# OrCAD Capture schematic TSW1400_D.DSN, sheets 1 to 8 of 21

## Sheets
1 BUTTON, SWITCH, LEDS: size B; title: BUTTONS, SWITCHES, LEDS; rev: D; note: TSW1400
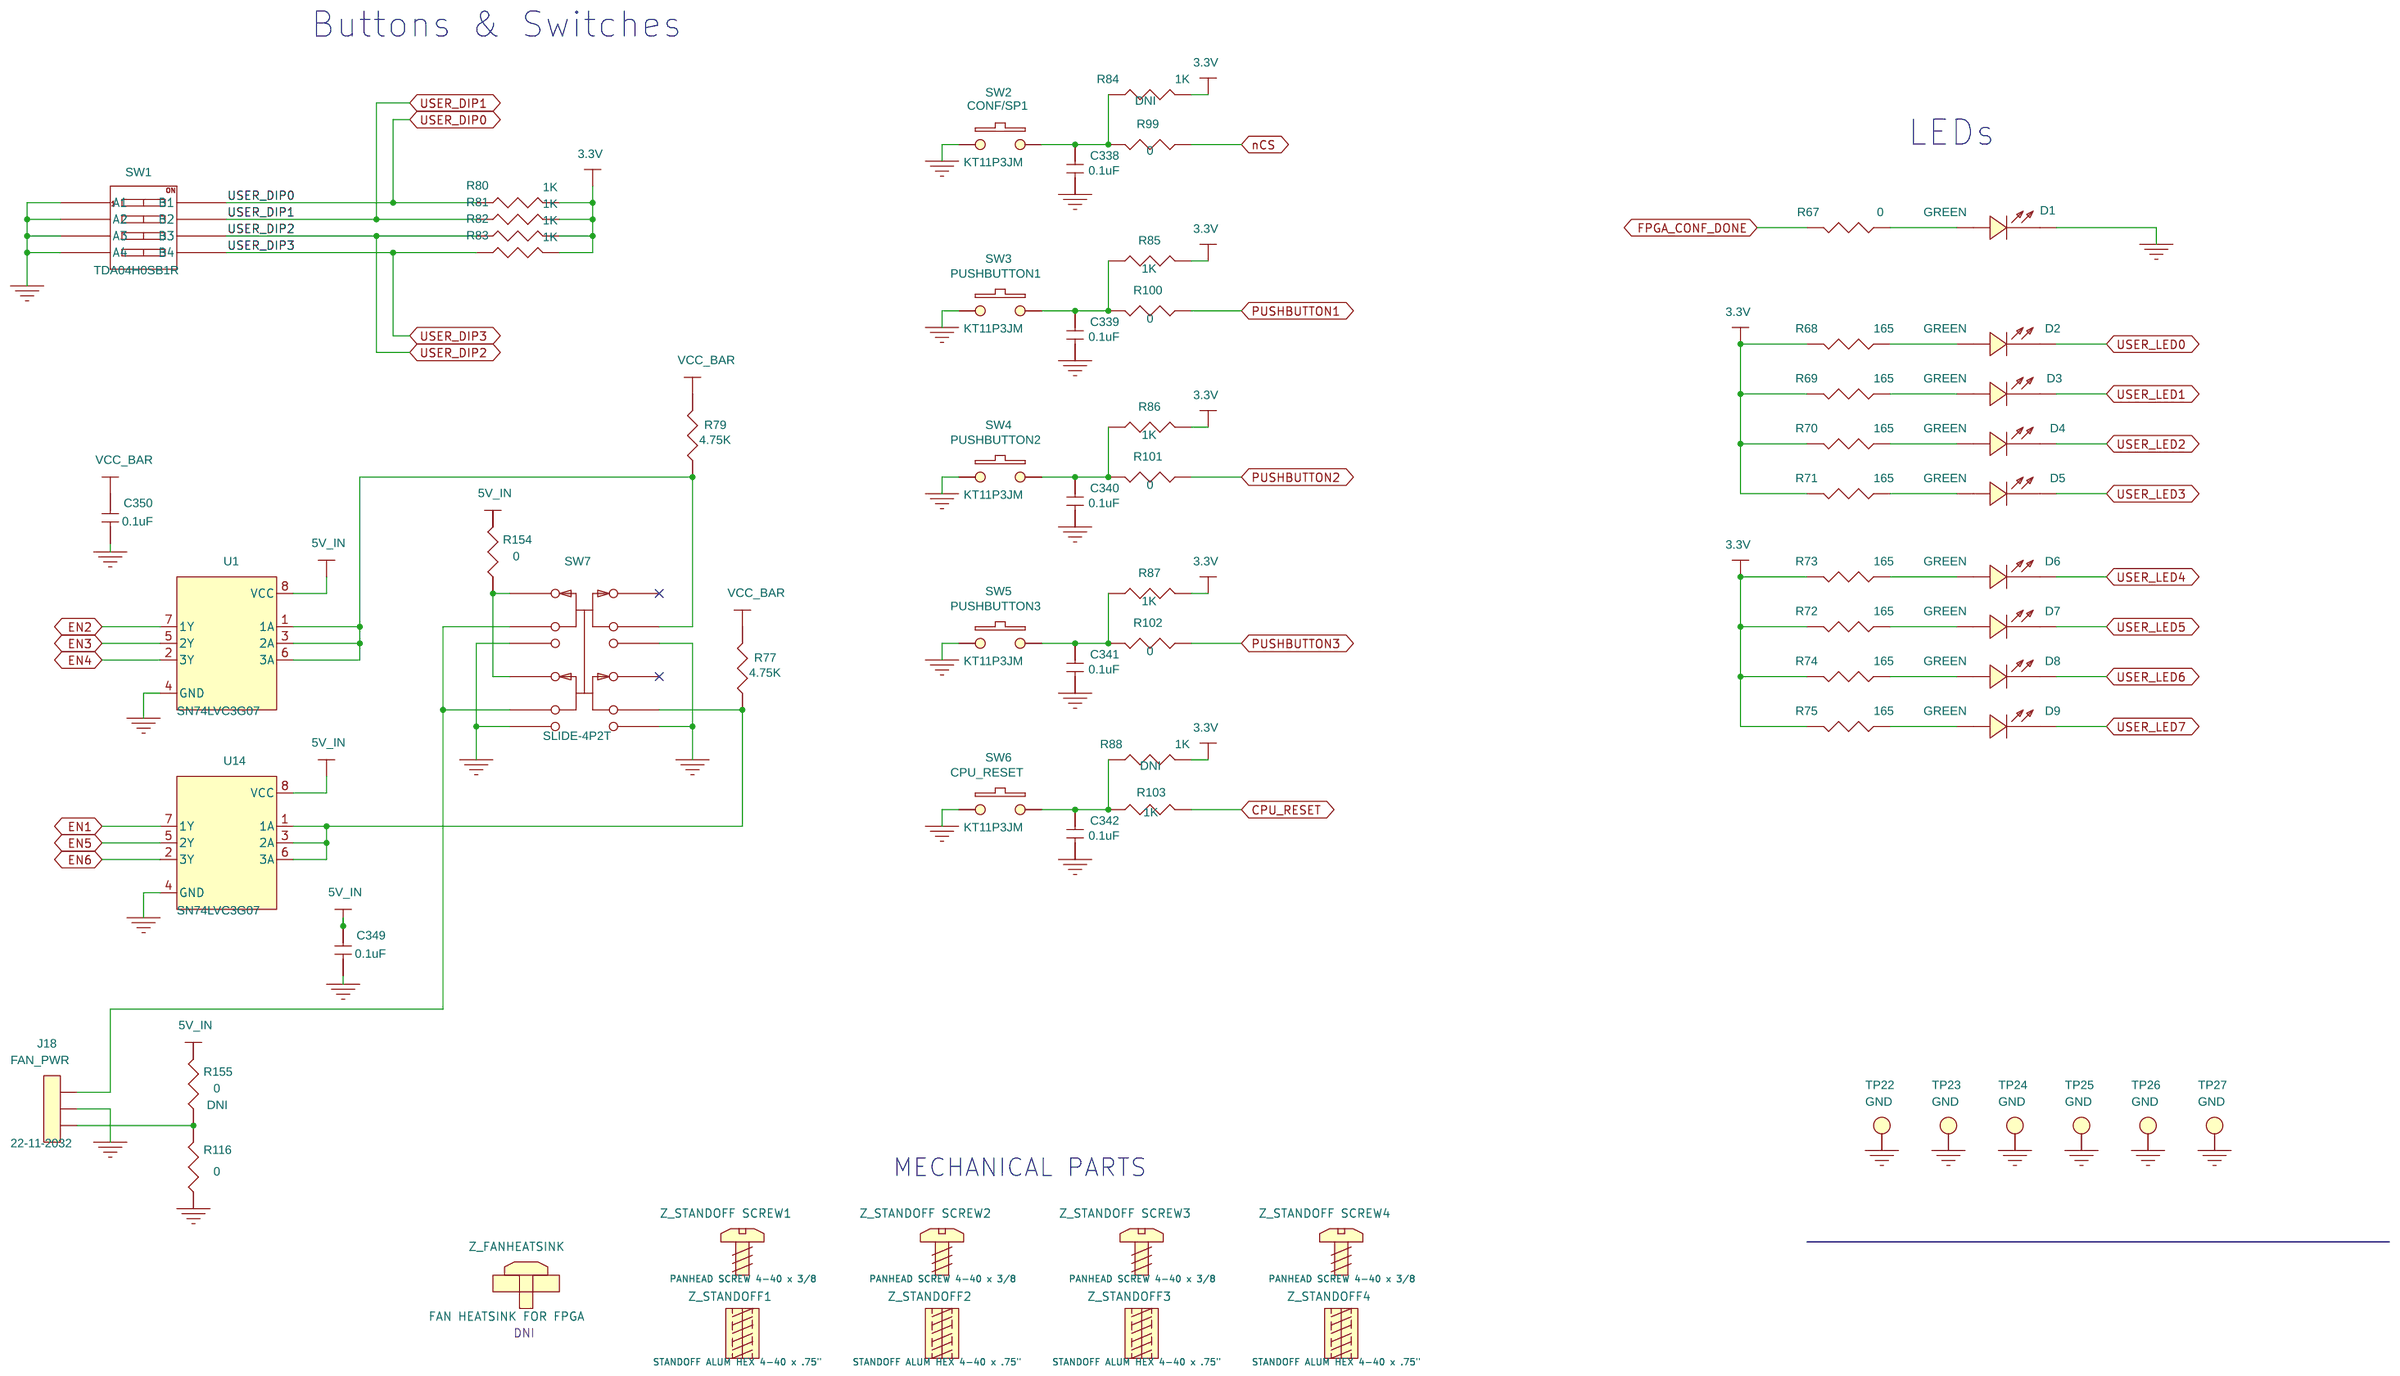
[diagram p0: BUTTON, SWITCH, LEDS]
2 CMOS Header: size B; title: CMOS Header
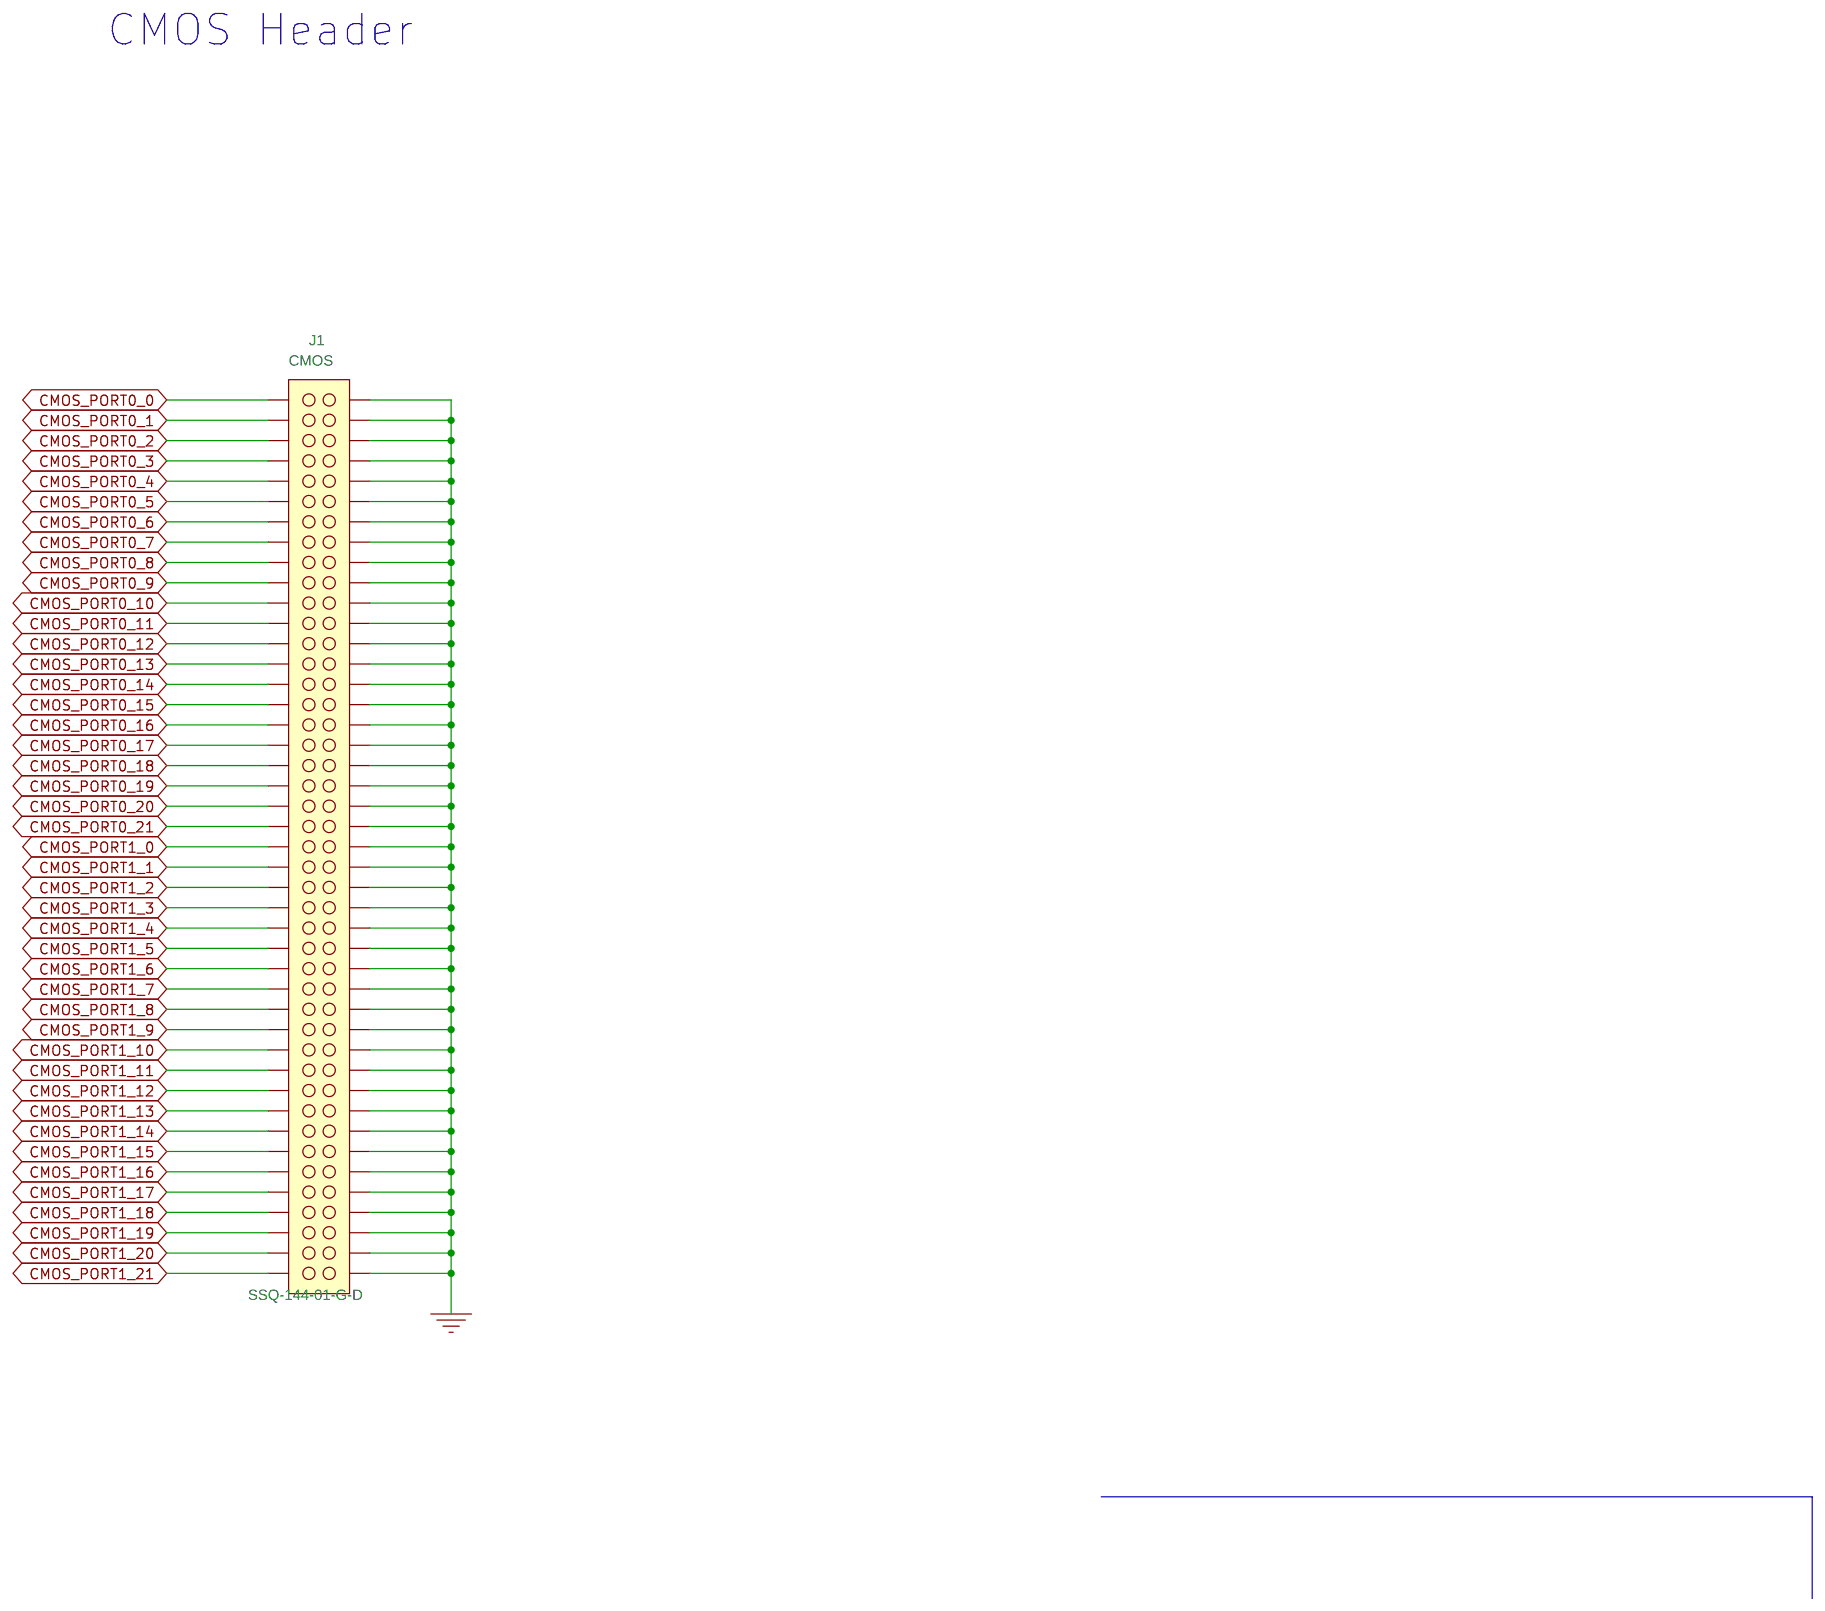
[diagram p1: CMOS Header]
3 ADC Interface: size B; title: ADC & JESD INTERFACE
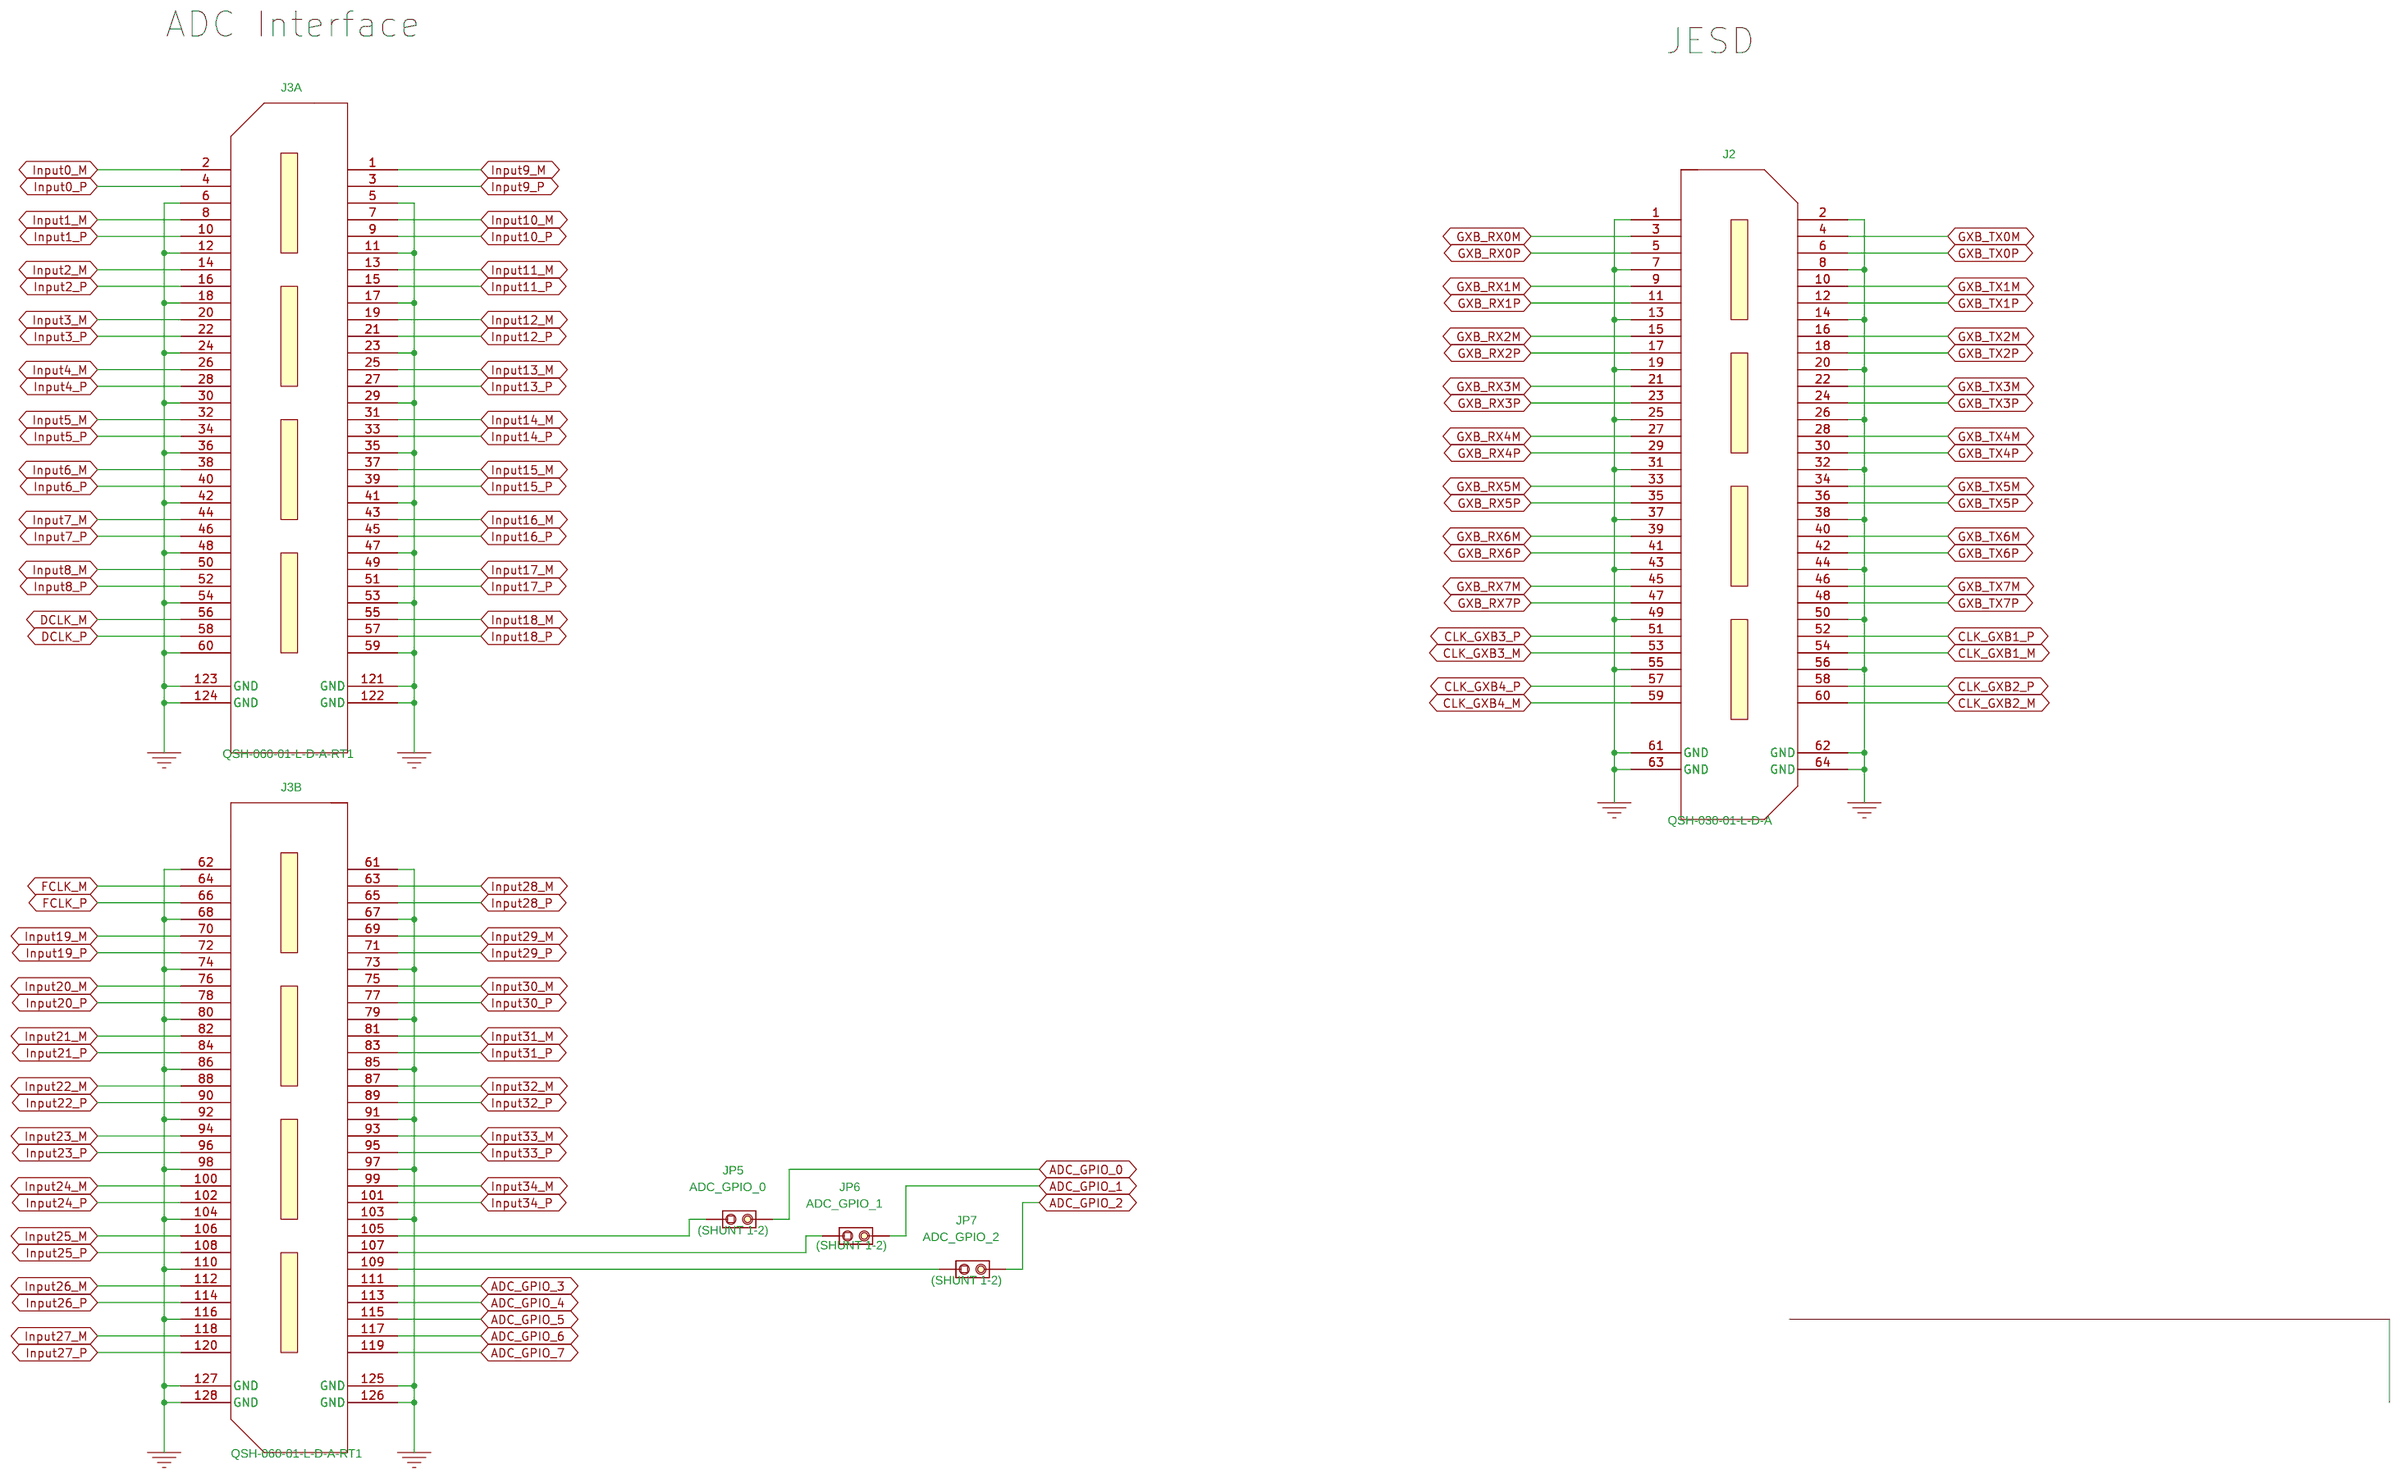
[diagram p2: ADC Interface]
4 DAC Interface: size B; title: DAC Interface
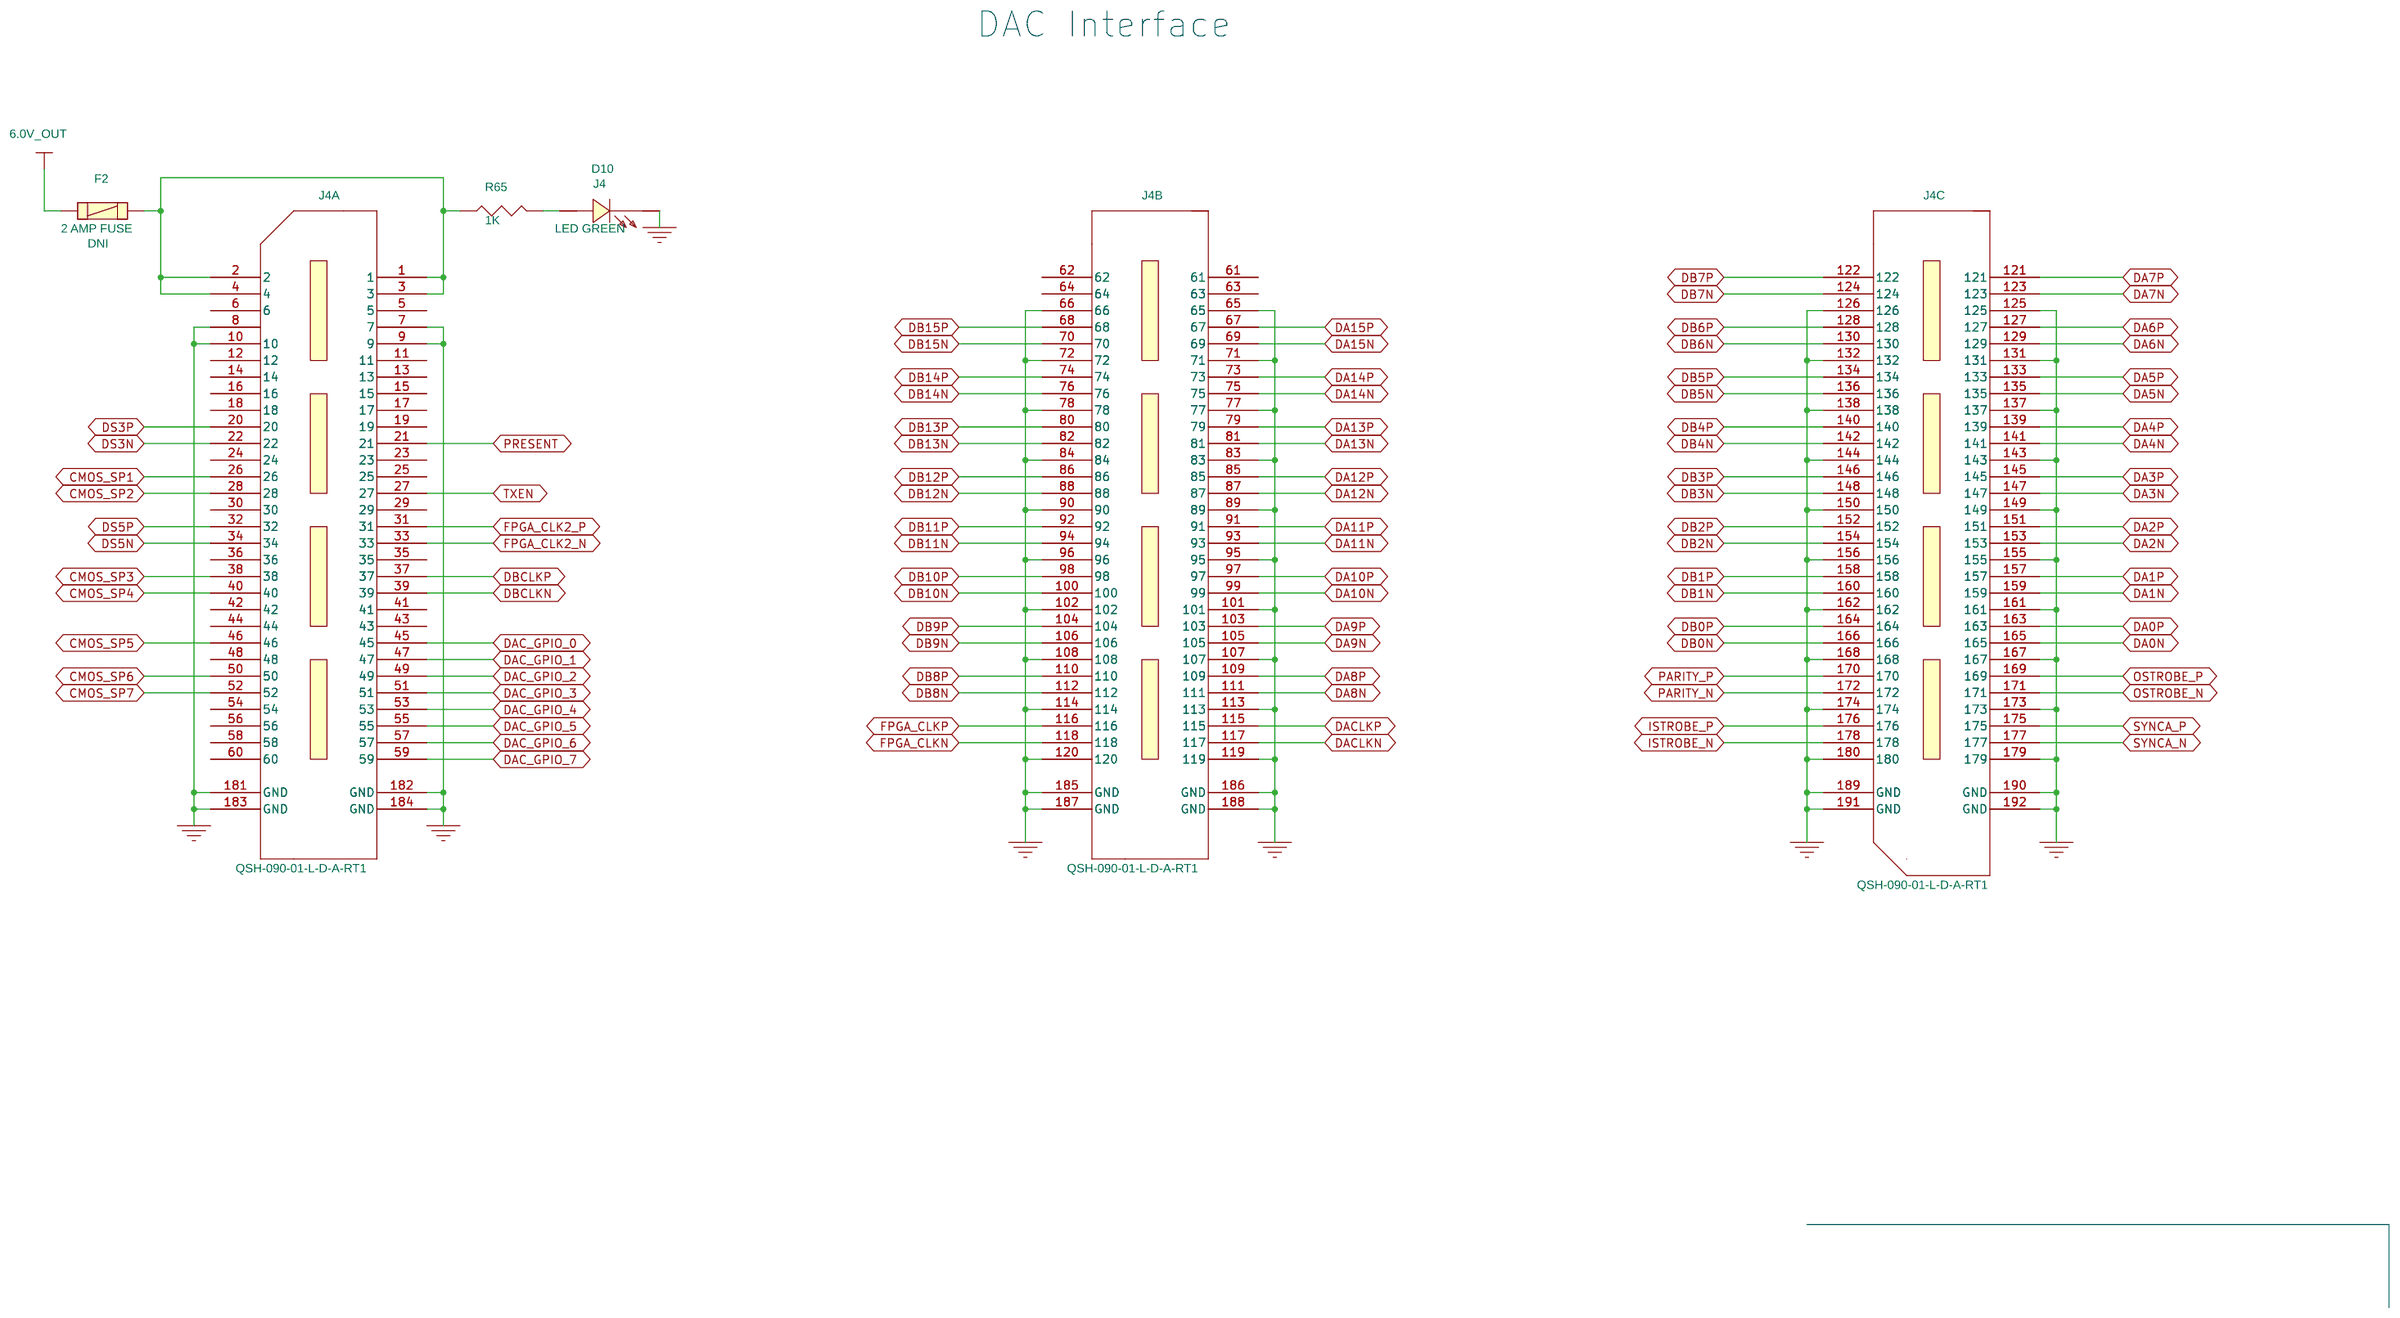
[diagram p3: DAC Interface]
5 USB: size B; title: USB
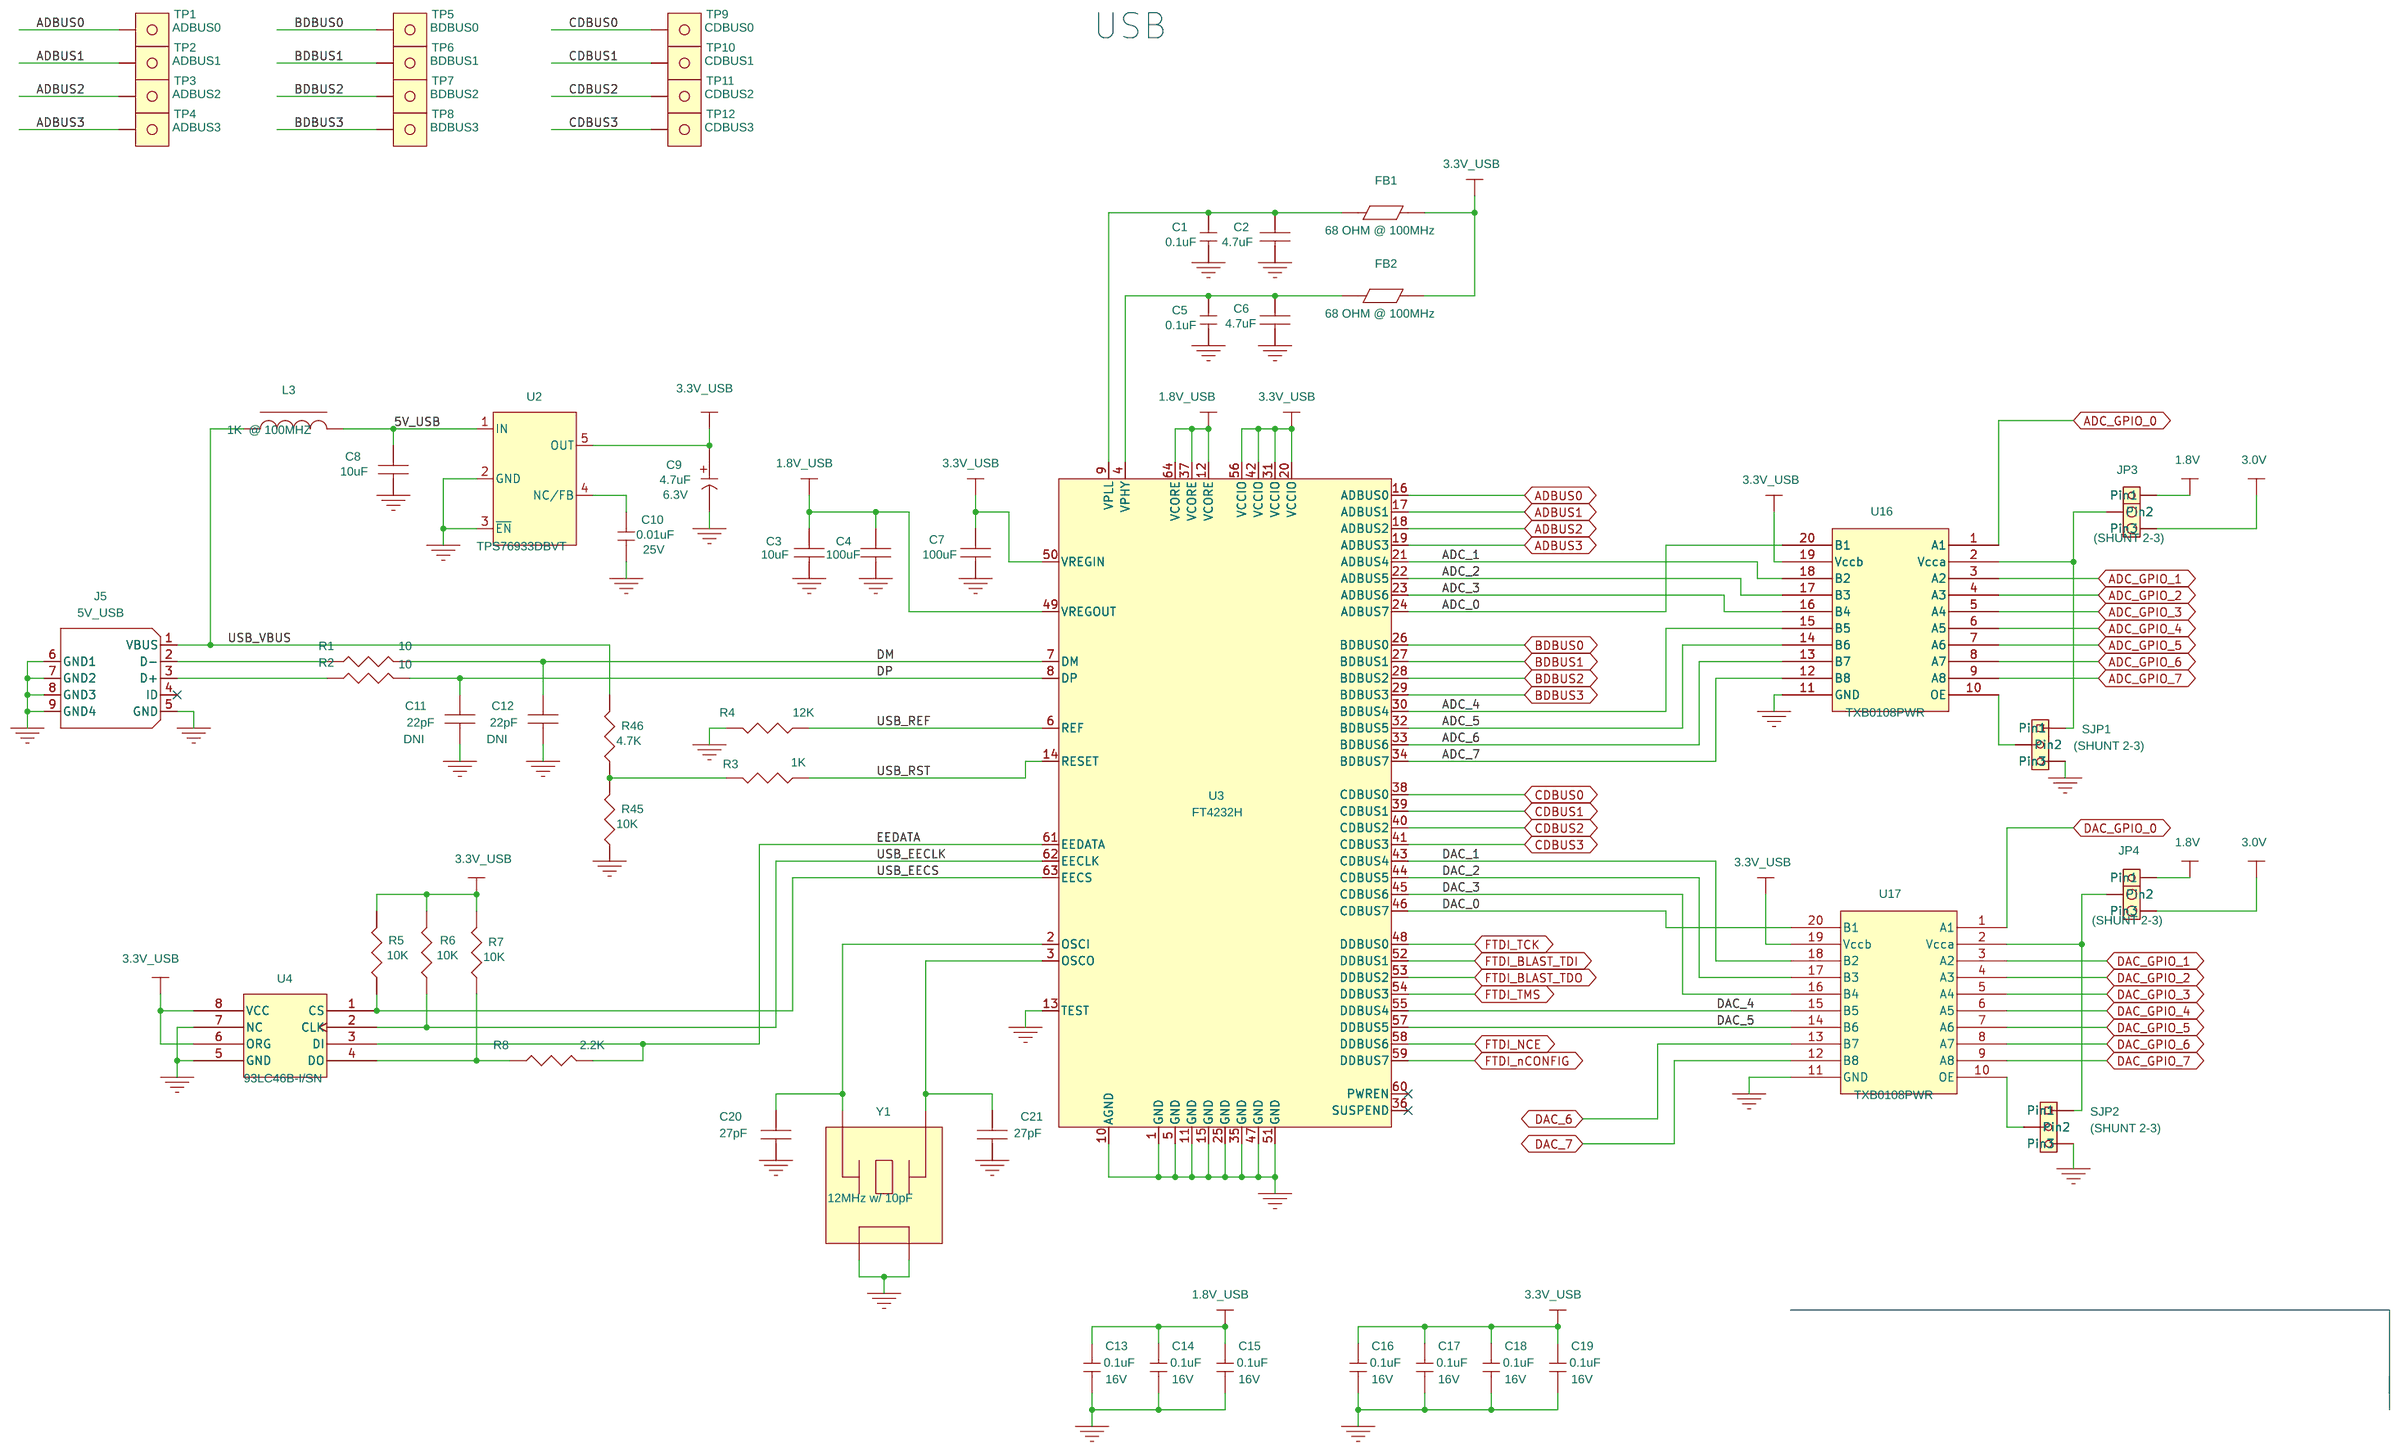
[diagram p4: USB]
6 DDR2 SO-DIMM: size C; title: DDR2 SO-DIMM
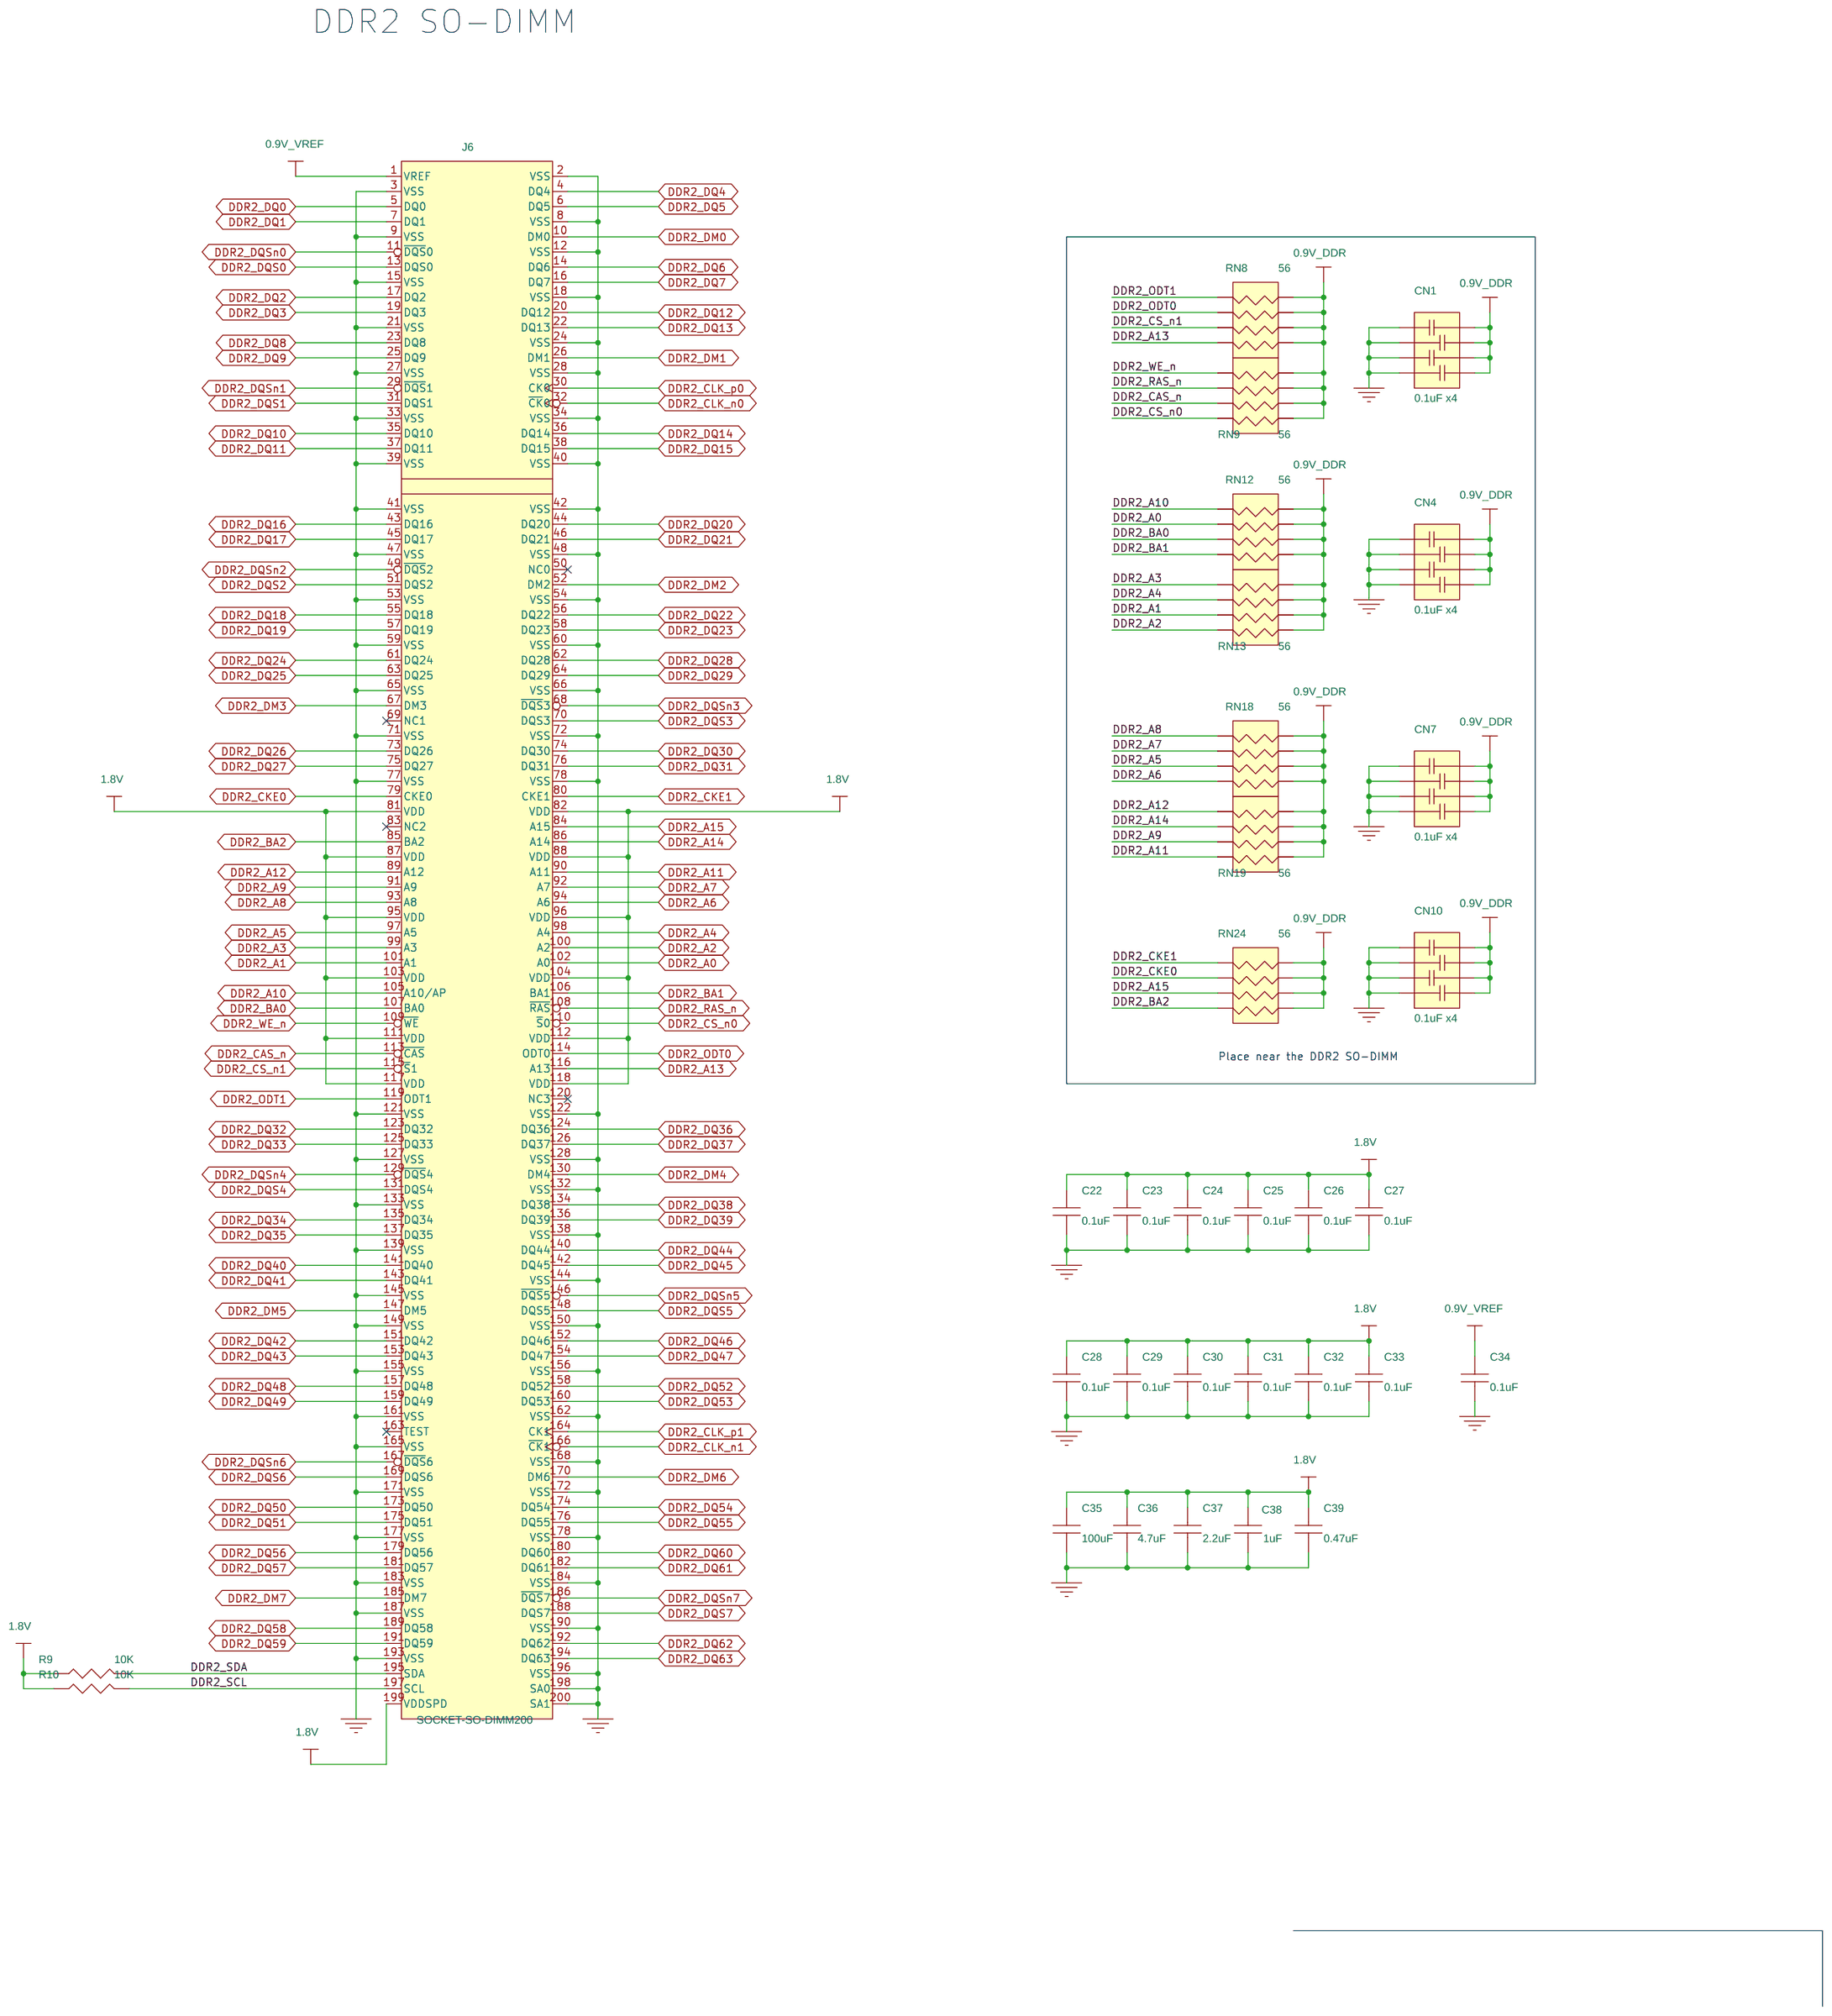
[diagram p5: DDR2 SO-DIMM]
7 Bank QL: size B; title: Bank QL
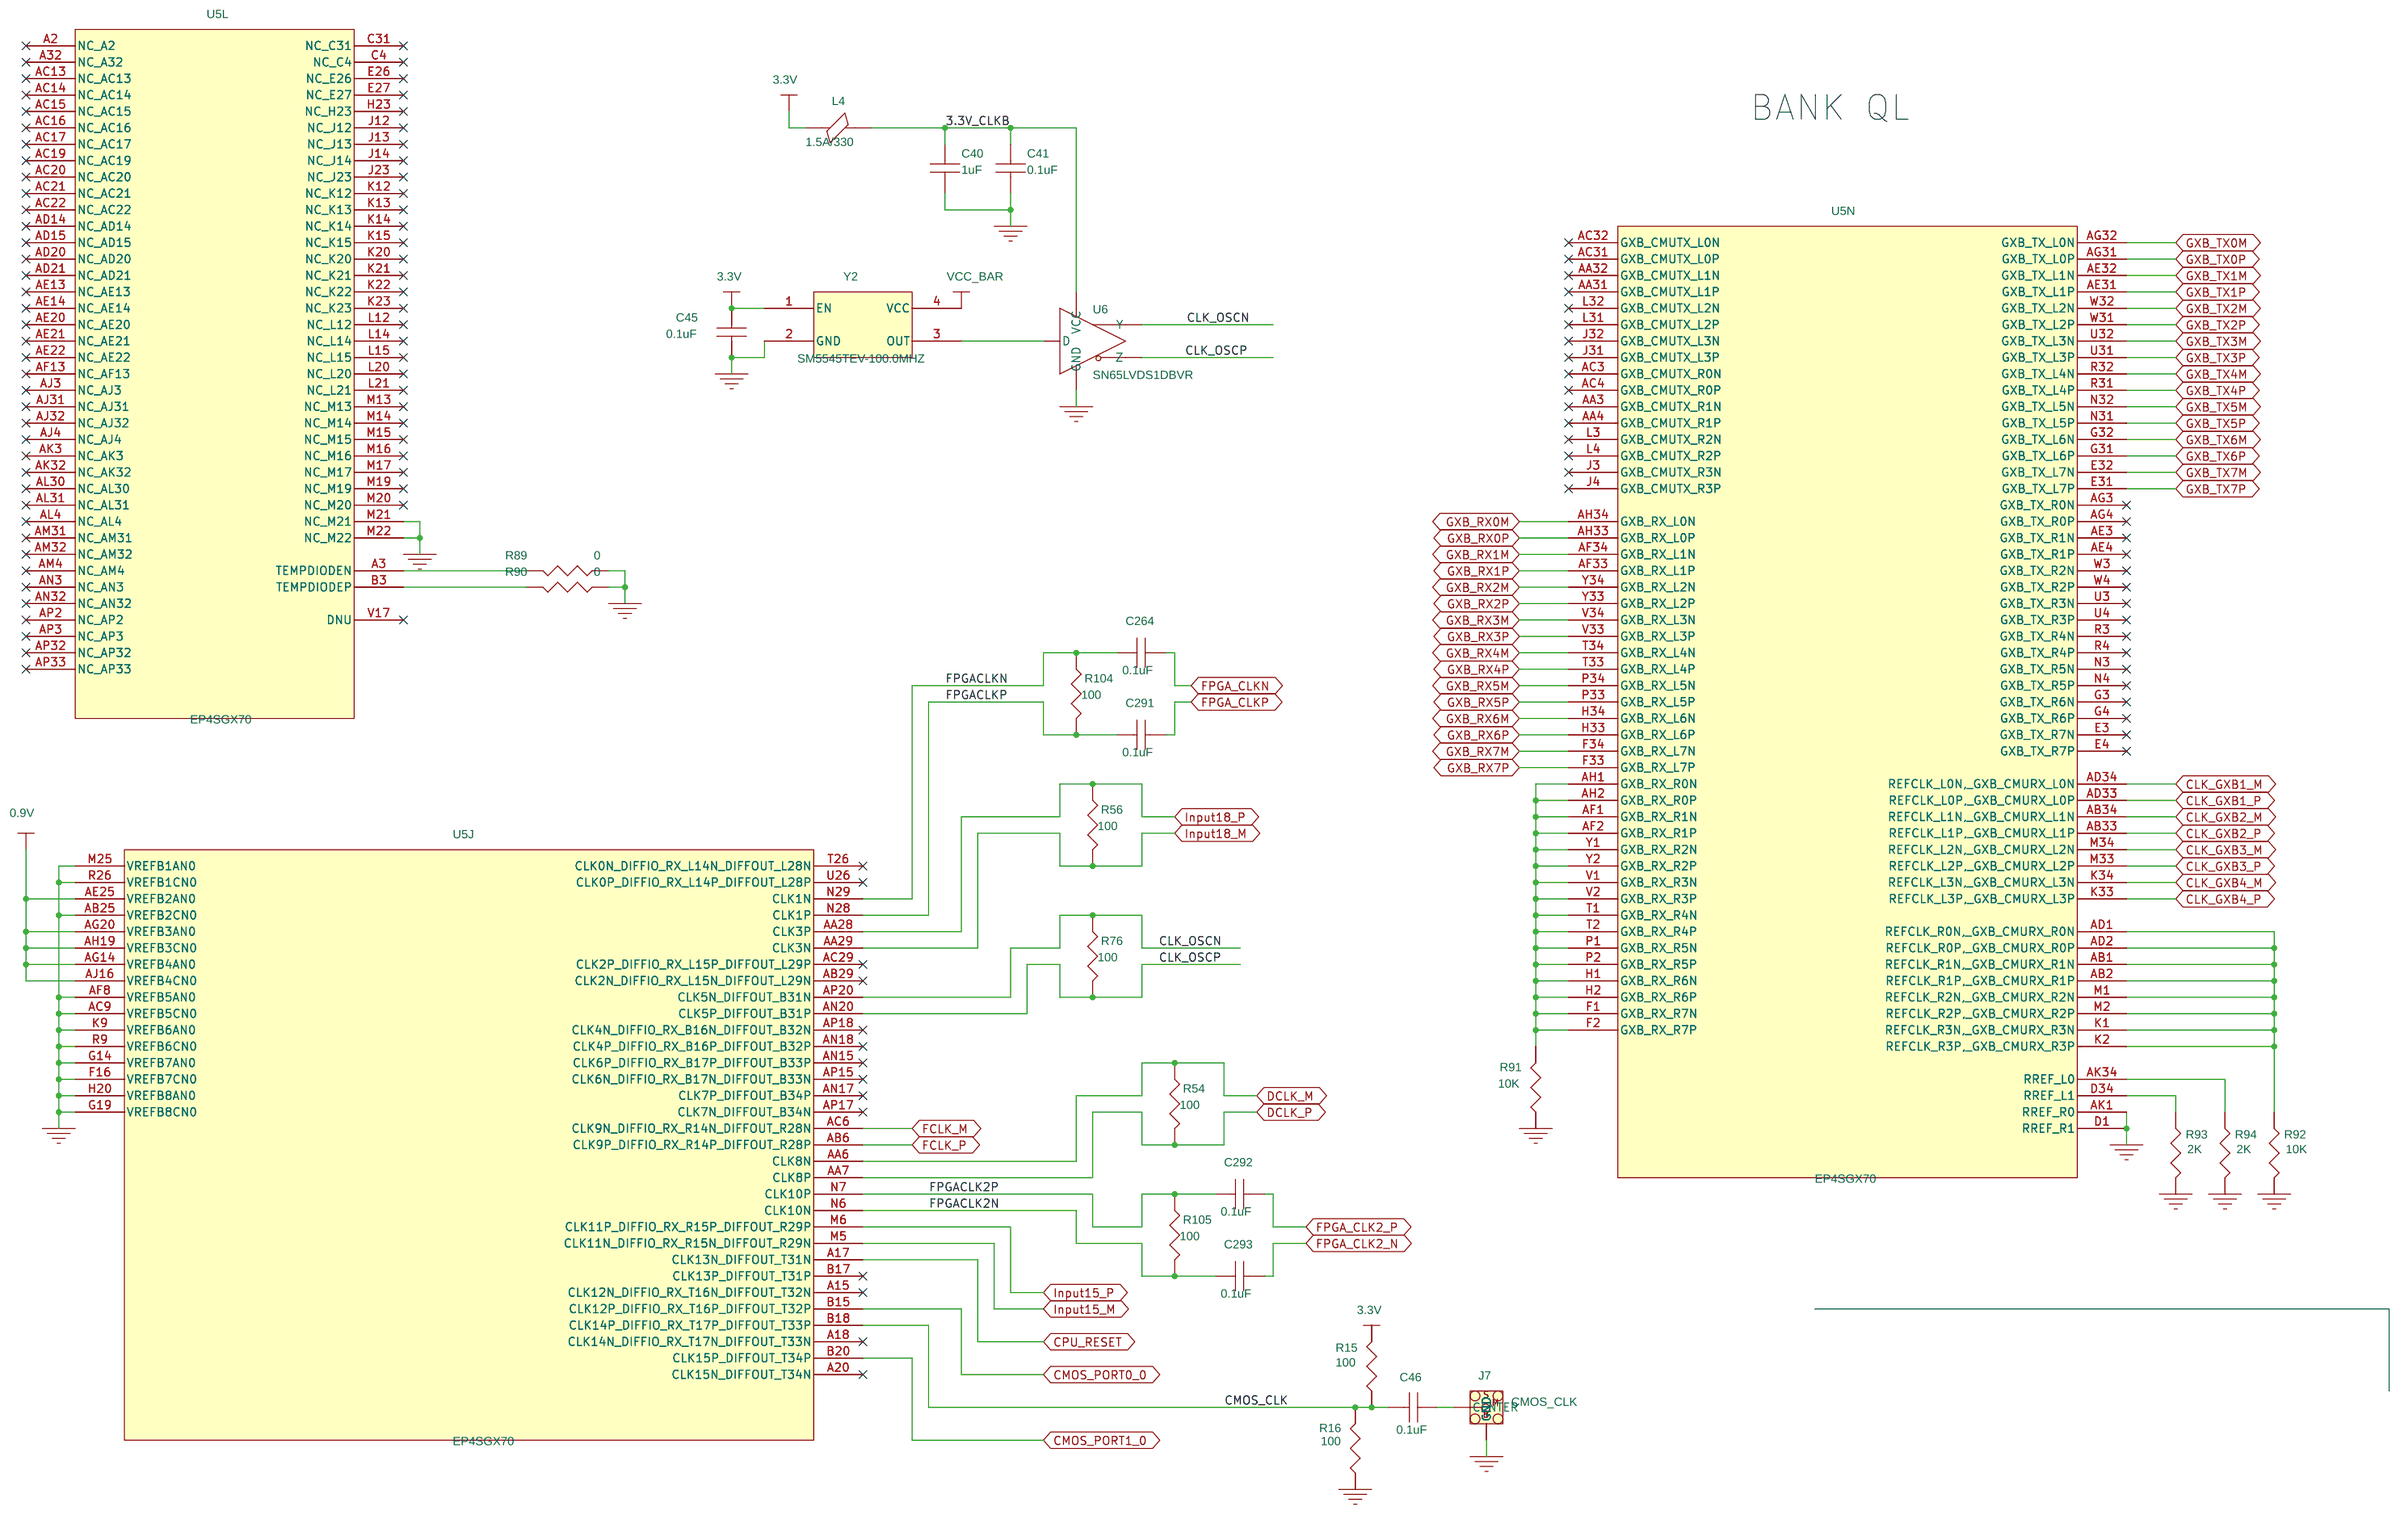
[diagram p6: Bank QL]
8 Bank 1: size B; title: Bank1
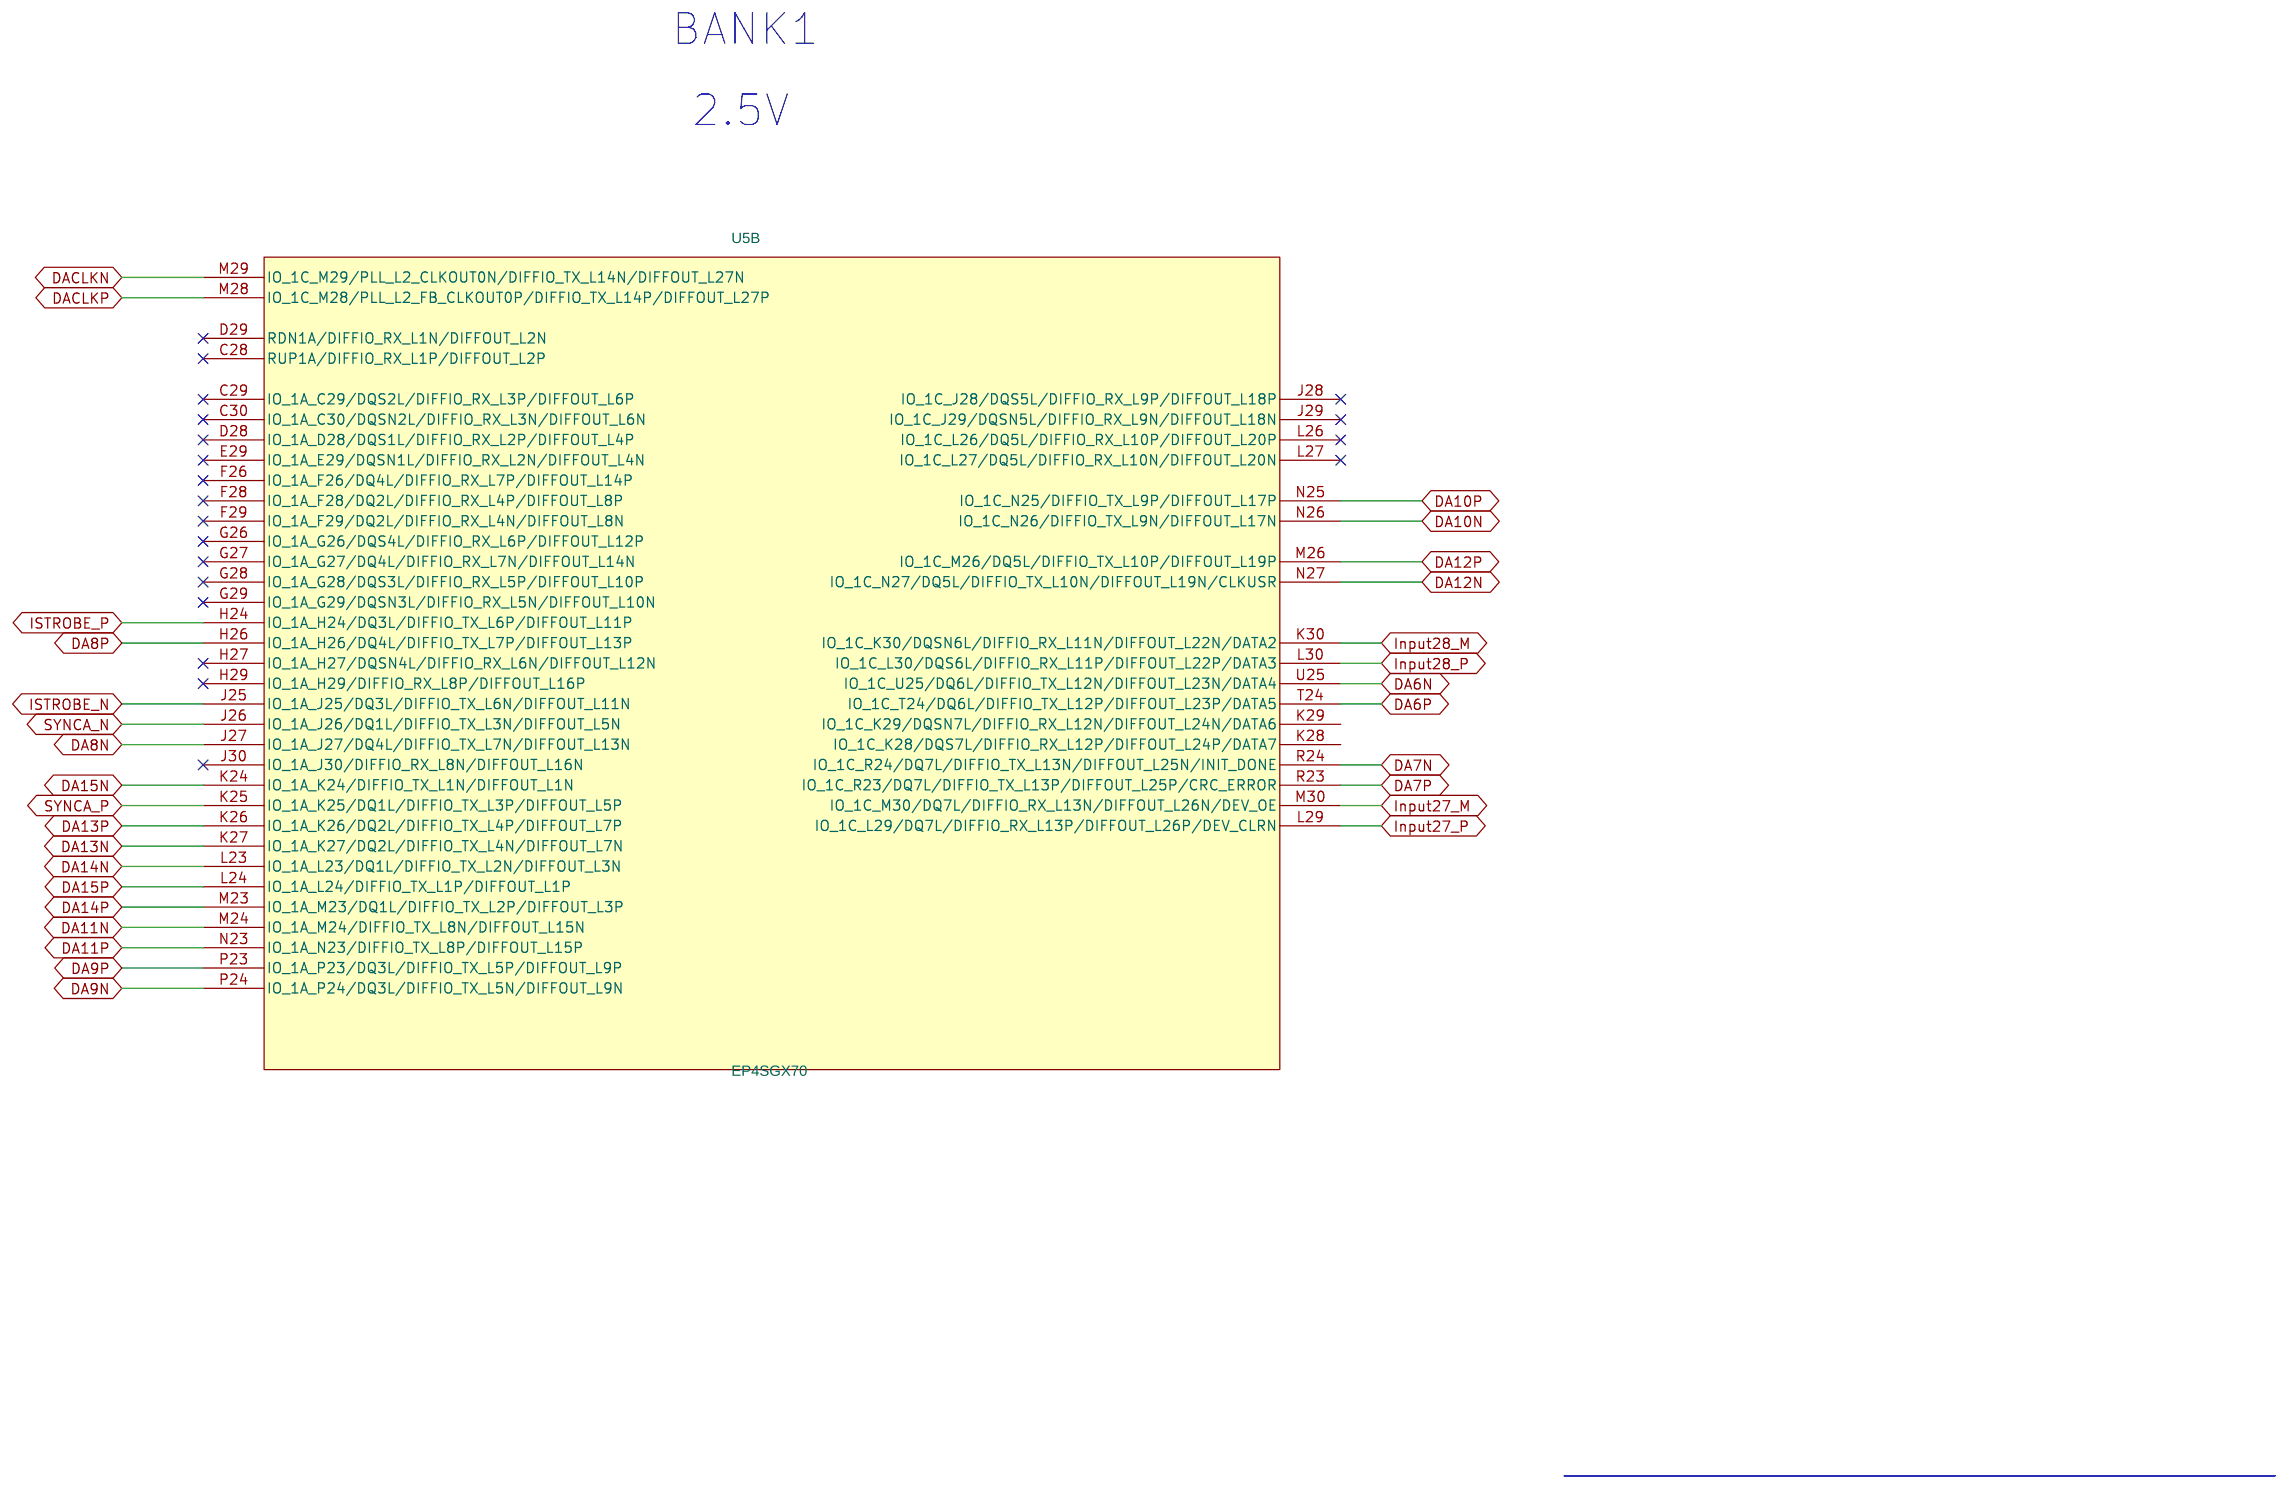
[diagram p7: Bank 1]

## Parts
sheet ADC Interface
J2  QSH-030-01-L-D-A  [CON_SMVT_60POS_QSH_SAMTEC]
J3  QSH-060-01-L-D-A-RT1  [CON_SMVT_120POS_QSH_SAMTEC_RT1]  (sections A,B)
JP5  JUMPER_1X2_100  [HDR_THVT_1X2_100_M]
JP6  JUMPER_1X2_100  [HDR_THVT_1X2_100_M]
JP7  JUMPER_1X2_100  [HDR_THVT_1X2_100_M]
Z_SH-H4  SHUNT- HEADER
Z_SH-H5  SHUNT- HEADER
Z_SH-H6  SHUNT- HEADER
sheet Bank6
U5  EP4SGX70  [BGA_1152_39]  (sections A,B,C,D,E,F,G,H,I,J,K,L,M,N)
sheet Bank QL
C40  1uF  [0402]
C41  0.1uF  [0402]
C45  0.1uF  [0402]
C46  0.1uF  [0603]
C264  0.1uF  [0402]
C291  0.1uF  [0402]
C292  0.1uF  [0402]
C293  0.1uF  [0402]
J7  SMB_THVT_REC  [SMA_THVT_312x312]
L4  1.5A/330  [IND_0805]
R15  100  [0603]
R16  100  [0603]
R54  100  [0201]
R56  100  [0201]
R76  100  [0402]
R89  0  [0402]
R90  0  [0402]
R91  10K  [0402]
R92  10K  [0402]
R93  2K  [0402]
R94  2K  [0402]
R104  100  [0201]
R105  100  [0201]
U6  SN65LVDS1DBVR  [SOP_5_118x67_37]
Y2  SM5545TEV-100.0MHZ  [OSC-3X5mm]
sheet BUTTON, SWITCH, LEDS
C338  0.1uF  [0603]
C339  0.1uF  [0603]
C340  0.1uF  [0603]
C341  0.1uF  [0603]
C342  0.1uF  [0603]
C349  0.1uF  [0402]
C350  0.1uF  [0402]
D1  GREEN  [LED_0805]
D2  GREEN  [LED_0805]
D3  GREEN  [LED_0805]
D4  GREEN  [LED_0805]
D5  GREEN  [LED_0805]
D6  GREEN  [LED_0805]
D7  GREEN  [LED_0805]
D8  GREEN  [LED_0805]
D9  GREEN  [LED_0805]
J18  22-11-2032  [HDR_THVT_1x3_100_M_KEYED]
R67  0  [0402]
R68  165  [0603]
R69  165  [0603]
R70  165  [0603]
R71  165  [0603]
R72  165  [0603]
R73  165  [0603]
R74  165  [0603]
R75  165  [0603]
R77  4.75K  [0402]
R79  4.75K  [0402]
R80  1K  [0402]
R81  1K  [0402]
R82  1K  [0402]
R83  1K  [0402]
R84  1K  [0402]
R85  1K  [0402]
R86  1K  [0402]
R87  1K  [0402]
R88  1K  [0402]
R99  0  [0402]
R100  0  [0402]
R101  0  [0402]
R102  0  [0402]
R103  1K  [0402]
R116  0  [0603]
R154  0  [0603]
R155  0  [0603]
SW1  TDA04H0SB1R  [SW-SMD-8]
SW2  KT11P3JM  [SW_SMVT_SPST_4]
SW3  KT11P3JM  [SW_SMVT_SPST_4]
SW4  KT11P3JM  [SW_SMVT_SPST_4]
SW5  KT11P3JM  [SW_SMVT_SPST_4]
SW6  KT11P3JM  [SW_SMVT_SPST_4]
SW7  SLIDE-4P2T  [SW_THVT_4PDT_SLIDE_12]
TP22  Testloop_Black  [TP_THVT_060_RND]
TP23  Testloop_Black  [TP_THVT_060_RND]
TP24  Testloop_Black  [TP_THVT_060_RND]
TP25  Testloop_Black  [TP_THVT_060_RND]
TP26  Testloop_Black  [TP_THVT_060_RND]
TP27  Testloop_Black  [TP_THVT_060_RND]
U1  SN74LVC3G07  [VSSOP_8_83X94_0P5MM]
U14  SN74LVC3G07  [VSSOP_8_83X94_0P5MM]
Z_FANHEATSINK  FAN HEATSINK FOR FPGA
Z_STANDOFF1  STANDOFF ALUM HEX 4-40 x .75"
Z_STANDOFF2  STANDOFF ALUM HEX 4-40 x .75"
Z_STANDOFF3  STANDOFF ALUM HEX 4-40 x .75"
Z_STANDOFF4  STANDOFF ALUM HEX 4-40 x .75"
Z_STANDOFF SCREW1  PANHEAD SCREW 4-40 x 3/8
Z_STANDOFF SCREW2  PANHEAD SCREW 4-40 x 3/8
Z_STANDOFF SCREW3  PANHEAD SCREW 4-40 x 3/8
Z_STANDOFF SCREW4  PANHEAD SCREW 4-40 x 3/8
sheet CMOS Header
J1  SSQ-144-01-G-D  [HDR_THVT_2x44_100_F]
sheet DAC Interface
D10  LED GREEN  [LED_0805]
F2  2 AMP FUSE  [FUSE_SM_NANO]
J4  QSH-090-01-L-D-A-RT1  [CON_SMVT_180POS_QSH_SAMTEC_RT1]  (sections A,B,C)
R65  1K  [0402]
sheet DDR2 SO-DIMM
C22  0.1uF  [0402]
C23  0.1uF  [0402]
C24  0.1uF  [0402]
C25  0.1uF  [0402]
C26  0.1uF  [0402]
C27  0.1uF  [0402]
C28  0.1uF  [0402]
C29  0.1uF  [0402]
C30  0.1uF  [0402]
C31  0.1uF  [0402]
C32  0.1uF  [0402]
C33  0.1uF  [0402]
C34  0.1uF  [0402]
C35  100uF  [1210]
C36  4.7uF  [0603]
C37  2.2uF  [0603]
C38  1uF  [0402]
C39  0.47uF  [0402]
CN1  0.1uF x4  [CA-AVE-0603-8]
CN4  0.1uF x4  [CA-AVE-0603-8]
CN7  0.1uF x4  [CA-AVE-0603-8]
CN10  0.1uF x4  [CA-AVE-0603-8]
J6  SOCKET-SO-DIMM200  [SOCKET-SO-DIMM200]
R9  10K  [0402]
R10  10K  [0402]
RN8  56  [RA-VEX-0402-8]
RN9  56  [RA-VEX-0402-8]
RN12  56  [RA-VEX-0402-8]
RN13  56  [RA-VEX-0402-8]
RN18  56  [RA-VEX-0402-8]
RN19  56  [RA-VEX-0402-8]
RN24  56  [RA-VEX-0402-8]
sheet USB
C1  0.1uF  [0603]
C2  4.7uF  [0603]
C3  10uF  [0603]
C4  100uF  [1206]
C5  0.1uF  [0603]
C6  4.7uF  [0603]
C7  100uF  [1206]
C8  10uF  [0603]
C9  4.7uF  [TANT_A]
C10  0.01uF  [0402]
C11  22pF  [0603]
C12  22pF  [0603]
C13  0.1uF  [0603]
C14  0.1uF  [0603]
C15  0.1uF  [0603]
C16  0.1uF  [0603]
C17  0.1uF  [0603]
C18  0.1uF  [0603]
C19  0.1uF  [0603]
C20  27pF  [0603]
C21  27pF  [0603]
FB1  68 OHM @ 100MHz  [1206]
FB2  68 OHM @ 100MHz  [1206]
J5  USB_MINI_AB_MNE20-5G5P10  [CON_SMRT_USBMNE20_F]
JP3  HEADER_1x3_100_430L  [HDR_THVT_1x3_100_M]
JP4  HEADER_1x3_100_430L  [HDR_THVT_1x3_100_M]
L3  1K  @ 100MHZ  [0805]
R1  10  [0603]
R2  10  [0603]
R3  1K  [0603]
R4  12K  [0603]
R5  10K  [0402]
R6  10K  [0402]
R7  10K  [0402]
R8  2.2K  [0402]
R45  10K  [0402]
R46  4.7K  [0402]
SJP1  SOLDER JUMPER, 0603  [SMD_JUMPER_1x3]
SJP2  SOLDER JUMPER, 0603  [SMD_JUMPER_1x3]
TP1  HMTSW-101-07-G-S-.240  [HDR_THVT_1x1]
TP2  HMTSW-101-07-G-S-.240  [HDR_THVT_1x1]
TP3  HMTSW-101-07-G-S-.240  [HDR_THVT_1x1]
TP4  HMTSW-101-07-G-S-.240  [HDR_THVT_1x1]
TP5  HMTSW-101-07-G-S-.240  [HDR_THVT_1x1]
TP6  HMTSW-101-07-G-S-.240  [HDR_THVT_1x1]
TP7  HMTSW-101-07-G-S-.240  [HDR_THVT_1x1]
TP8  HMTSW-101-07-G-S-.240  [HDR_THVT_1x1]
TP9  HMTSW-101-07-G-S-.240  [HDR_THVT_1x1]
TP10  HMTSW-101-07-G-S-.240  [HDR_THVT_1x1]
TP11  HMTSW-101-07-G-S-.240  [HDR_THVT_1x1]
TP12  HMTSW-101-07-G-S-.240  [HDR_THVT_1x1]
U2  TPS76933DBVT  [SOT_5_118x67_57]
U3  FT4232H  [LQFP_64_402x402_20]
U4  93LC46B-I/SN  [SOIC-8]
U16  TXB0108PWR  [TSSOP_20_260x177_26]
U17  TXB0108PWR  [TSSOP_20_260x177_26]
Y1  12MHz w/ 10pF  [XTAL_4_SM_130x102]
Z_SH-H1  SHUNT-HEADER
Z_SH-H2  SHUNT-HEADER
Z_SH-J1  SHUNT-JUMPER-0603  [0603]
Z_SH-J2  SHUNT-JUMPER-0603  [0603]

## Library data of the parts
J2 = CON_SMVT_60POS_QSH_SAMTEC_0: Mfr_Name: Samtec
J3 = CON_SMVT_120POS_QSH_SAMTEC: Mfr_Name: Samtec
JP5 = JUMPER_1x2_100: Mfr_Name: Samtec; Note: (SHUNT 1-2); TI_Silktext: ADC_GPIO_0
JP6 = JUMPER_1x2_100: Mfr_Name: Samtec; Note: (SHUNT 1-2); TI_Silktext: ADC_GPIO_1
JP7 = JUMPER_1x2_100: Mfr_Name: Samtec; Note: (SHUNT 1-2); TI_Silktext: ADC_GPIO_2
Z_SH-H4-Z_SH-H6 = SHUNT-HEADER_-_2POS: Mfr_Name: Keltron; Mfr_Part_Number: MJ-5.97-G or equivalent; Note: SHUNT FOR HEADER
U5 = EP4SGX70F1152_2
C40 = CAPACITOR_NP_1: Mfr_Name: Murata; Mfr_Part_Number: GRM155R61A105KE15D; Tolerance: 10%; Voltage: 10V
C22-C34 C41 C45 C264 C291-C293 = CAP: Mfr_Name: Murata; Mfr_Part_Number: GRM155R61A104KA01D; Package: SMD; Type: Capacitor
C46 = CAP_0603: Mfr_Name: Murata; Mfr_Part_Number: GRM188R71C104KA01D
J7 = SMA-THVT_142-0701-201_REC: TI_Silktext: CMOS_CLK
L4 = BEAD_FERRITE_SM_1: Mfr_Name: TDK; Mfr_Part_Number: MPZ2012S331A
R15 R16 = RES_0603: Mfr_Name: Panasonic; Mfr_Part_Number: ERJ-3EKF1000V
R54 R56 R104 R105 = RES_0603: Mfr_Name: Panasonic; Mfr_Part_Number: ERJ-1GEF1000C
R76 = RES_0603: Mfr_Name: Panasonic; Mfr_Part_Number: ERJ-2RKF1000X
R89 R90 R99 = Res_0402_Zero: Mfr_Name: Panasonic; Mfr_Part_Number: ERJ-2GE0R00X
R91 R92 = res_smd_0: Mfr_Name: Panasonic; Mfr_Part_Number: ERJ-2RKF1002X
R93 R94 = res_smd_0: Mfr_Name: Panasonic; Mfr_Part_Number: ERJ-2RKF2001X
U6 = SN65LVDS1DBVR
Y2 = OSC: 100MHz, 25ppm, CL=15pF, 3.3V, Size=3X5 mm; Mfr_Name: Pletronics; Mfr_Part_Number: SM5545TEV-100.0M; Package: SMD; Terasic_Prt: M0923; Type: Crystal
C1 C5 C13-C19 C338-C342 = CAP0603: Mfr_Name: Murata; Mfr_Part_Number: GRM188R71C104KA01D; PART_NUMBER: ECJ-1VB1C104K; TOL: 10%; Voltage: 16V
C349 C350 = CAP_0402_0.1uF: Mfr_Name: Murata
D1-D9 = LED: Green LED; Mfr_Name: Liteon; Mfr_Part_Number: LTST-C170KGKT; Package: SMD; Terasic_Prt: M0200
J18 = CON_THVT_MOLEX_22-23-2031: Mfr_Name: Molex; TI_SILKTEXT: FAN_PWR
R67 R100-R102 = Res_0402_Zero: Mfr_Name: Panasonic
R68-R75 = RES0603: Mfr_Name: Panasonic; Mfr_Part_Number: ERJ-3EKF1650V
R77 R79 = RESISTOR: Mfr_Name: Panasonic; Mfr_Part_Number: ERJ-2RKF4751X; Type: Resistor
R80-R83 R85-R87 R103 = RES: Mfr_Name: Panasonic; Mfr_Part_Number: ERJ-2RKF1001X
R84 R88 = RES: Mfr_Name: Panasonic; Mfr_Part_Number: ERJ-2RKF1001X_DNI; Note: DNI
R116 R154 = RES: Mfr_Name: Panasonic; Mfr_Part_Number: ERJ-3GEY0R00V; Type: Resistor
R155 = RES: Mfr_Name: Panasonic; Mfr_Part_Number: ERJ-3GEY0R00V_DNI; Note: DNI; Type: Resistor
SW1 = SW-DIP8: SMD DIP Switch 4 PoleS, Pitch = 1.27 mm, L6.6*W8*T2.5 mm; Mfr_Name: CK Components; Package: SMD; Terasic_Prt: M0759; Type: Switch
SW2 = SW_SMVT_SPST_4_KT11P3JM: Mfr_Name: ITT Industries; TI_SILKTEXT: CONF/SP1
SW3 = SW_SMVT_SPST_4_KT11P3JM: Mfr_Name: ITT Industries; TI_SILKTEXT: PUSHBUTTON1
SW4 = SW_SMVT_SPST_4_KT11P3JM: Mfr_Name: ITT Industries; TI_SILKTEXT: PUSHBUTTON2
SW5 = SW_SMVT_SPST_4_KT11P3JM: Mfr_Name: ITT Industries; TI_SILKTEXT: PUSHBUTTON3
SW6 = SW_SMVT_SPST_4_KT11P3JM: Mfr_Name: ITT Industries; TI_SILKTEXT: CPU_RESET
SW7 = SW_SLIDE-4P2T_1: Slide Switch; Mfr_Name: E-SWITCH; Mfr_Part_Number: EG4208A
TP22-TP27 = TP_THVT_060_RND-BLK: Mfr_Name: Components Corporation; Mfr_Part_Number: TP-105-01-00; TI_SILKTEXT: GND
U1 U14 = SN74LVC3G07DCU: Mfr_Name: Texas Instruments
Z_FANHEATSINK = HEATSINK: Mfr_Name: RADIAN HEATSINKS; Mfr_Part_Number: FB3L3_DNI; Note: DNI
Z_STANDOFF1-Z_STANDOFF4 = STANDOFF: Mfr_Name: Keystone; Mfr_Part_Number: 2204
Z_STANDOFF SCREW1-Z_STANDOFF SCREW4 = SCREW-STANDOFF: Mfr_Part_Number: PMSSS 440 0038 PH
J1 = HEADER_2x44_100: Mfr_Name: Samtec; TI_SILKTEXT: CMOS
D10 = LED: Mfr_Name: Panasonic; Mfr_Part_Number: LNJ306G5UUX; PART_NUMBER: Panasonic LNJ306G5UUX; TI_Silktext: J4
F2 = LITTELFUSE_0154007: Mfr_Part_Number: 0154002.DR_DNI; Note: DNI
J4 = CON_SMVT_180POS_QSH_SAMTEC: Mfr_Name: Samtec
R65 = R_0: Mfr_Name: Panasonic; Mfr_Part_Number: ERJ-2RKF1001X; TOL: 1%
C35 = CAP: Mfr_Name: Murata; Mfr_Part_Number: GRM32ER60J107ME20L; TOL: 20%; VOLTAGE: 6.3V
C2 C6 C36 = CAP_NP_0: Mfr_Name: Kemet; Mfr_Part_Number: C0603C475K8PACTU; TOL: 10%; VOLTAGE: 10V
C37 = CAP: 2.2uF, +/-10%, 10V, X5R(0603); Mfr_Name: Yageo; Mfr_Part_Number: CC0603KRX5R6BB225; Package: SMD; Terasic_Prt: MCC-2000-YGO; Type: Capacitor
C38 = CAP: Mfr_Name: Murata; Mfr_Part_Number: GRM155R61A105KE15D; Tolerance: 10%; Voltage: 10V
C39 = CAP: Mfr_Name: Murata; Mfr_Part_Number: GRM155F51A474ZE01D
CN1 CN4 CN7 CN10 = CA: CAP - 4 ARRAY, 0.1UF, 25V, Y5V, -20/+80%; Mfr_Name: AVX; Mfr_Part_Number: W3A4YC104KAT2A; Package: SMD; Terasic_Prt: M0643; Type: Capacitor
J6 = SOCKET-SO-DIMM200: Mfr_Name: Tyco; Mfr_Part_Number: 1473005-4
R9 R10 = RES: Mfr_Name: Panasonic; Mfr_Part_Number: ERJ-2RKF1002X; Type: Resistor
RN8 RN9 RN12 RN13 RN18 RN19 RN24 = RA-8P4R: 56 ohm, +/-5%, 1/16W, 8P4R, Convex(0402*4); Mfr_Name: Yageo; Mfr_Part_Number: YC124-JR-0756R; Package: SMD; Terasic_Prt: M1241; Type: Resistor
C3 C8 = CAP_NP: Mfr_Name: Murata; Mfr_Part_Number: GRM188R60J106ME47D; TOL: 20%; VOLTAGE: 6.3V
C4 C7 = CAP_NP: Mfr_Name: Kemet; Mfr_Part_Number: C1206C107M9PACTU; TOL: 20%; VOLTAGE: 6.3V
C9 = CAP_POL-A: Mfr_Name: AVX; Mfr_Part_Number: TAJA475K006RNJ; TOL: 10%; Voltage: 6.3V
C10 = CAP0402: Mfr_Name: Murata; Mfr_Part_Number: GRM155R71E103KA01D; TOL: +/-10%; Voltage: 25V
C11 C12 = CAP_NP: Mfr_Name: Murata; Mfr_Part_Number: GRM1885C2A220JA01D_DNI; Note: DNI; PART_NUMBER: GRM1885C2A220JA01D; TOL: 5%; VOLTAGE: 100V
C20 C21 = CAP_NP: GROUP: NOT INSTALLED; Mfr_Name: Murata; Mfr_Part_Number: ERB1885C2E270JDX5D; PART_NUMBER: GRM1885C2A330JA01D; TOL: 5%; VOLTAGE: 100V
FB1 FB2 = FERRITE_BEAD: Mfr_Name: Panasonic; Mfr_Part_Number: EXC-ML32A680U; PART_NUMBER: Panasonic EXC-ML32A680U
J5 = USB_MINI_AB_MNE20-5G5P10: Mfr_Name: ACON; Mfr_Part_Number: MNE20-5G5P10; TI_SILKTEXT: 5V_USB
JP3 JP4 = JUMPER_1x3_100: Mfr_Name: Samtec; Note: (SHUNT 2-3); TI_Silktext: <TI_Silktext>
L3 = FERRITE_BEAD_0: CLASS: DISCRETE; Mfr_Name: Murata; Mfr_Part_Number: BLM21AG102SN1D
R1 = R: Mfr_Name: Yageo; Mfr_Part_Number: RC0603FR-0710RL; PART_NUMBER: RC0603FR-0733RL; TOL: 1%; Wattage: 1/10W
R2 = R: Mfr_Name: Yageo; Mfr_Part_Number: RC0603FR-0733RL; PART_NUMBER: RC0603FR-0733RL; TOL: 1%; Wattage: 1/10W
R3 = R: Mfr_Name: Panasonic; Mfr_Part_Number: ERJ-3EKF1001V
R4 = R: Mfr_Name: Panasonic; Mfr_Part_Number: ERJ-3EKF1202V; PART_NUMBER: ERJ-3EKF1202V; TOL: 1%
R5-R7 R45 = RESISTOR: Mfr_Name: Panasonic; Mfr_Part_Number: ERJ-2RKF1002X; Type: Resistor
R8 = RESISTOR: Mfr_Name: Panasonic; Mfr_Part_Number: ERJ-2RKF2201X; Type: Resistor
R46 = RESISTOR: Mfr_Name: Panasonic; Mfr_Part_Number: ERJ-2RKF4701X; Type: Resistor
SJP1 SJP2 = JUMPER_SMD_1X3: Note: (SHUNT 2-3); TI_Silktext: <TI_Silktext>
TP1 = HEADER_1x1: Mfr_Name: Samtec; TI_SILKTEXT: ADBUS0
TP2 = HEADER_1x1: Mfr_Name: Samtec; TI_SILKTEXT: ADBUS1
TP3 = HEADER_1x1: Mfr_Name: Samtec; TI_SILKTEXT: ADBUS2
TP4 = HEADER_1x1: Mfr_Name: Samtec; TI_SILKTEXT: ADBUS3
TP5 = HEADER_1x1: Mfr_Name: Samtec; TI_SILKTEXT: BDBUS0
TP6 = HEADER_1x1: Mfr_Name: Samtec; TI_SILKTEXT: BDBUS1
TP7 = HEADER_1x1: Mfr_Name: Samtec; TI_SILKTEXT: BDBUS2
TP8 = HEADER_1x1: Mfr_Name: Samtec; TI_SILKTEXT: BDBUS3
TP9 = HEADER_1x1: Mfr_Name: Samtec; TI_SILKTEXT: CDBUS0
TP10 = HEADER_1x1: Mfr_Name: Samtec; TI_SILKTEXT: CDBUS1
TP11 = HEADER_1x1: Mfr_Name: Samtec; TI_SILKTEXT: CDBUS2
TP12 = HEADER_1x1: Mfr_Name: Samtec; TI_SILKTEXT: CDBUS3
U2 = TPS769XX-SOT23_0: Mfr_Name: Texas Instruments
U3 = FT4232H_2
U4 = EEPROM: 93LC46B-I/SN,Serial EEPROM, 64 x 16bit, 2.5V-5.5V; Mfr_Name: Microchip; Package: SMD; Terasic_Prt: M0252; Type: Memory
U16 U17 = TXB0108PWR
Y1 = CRYSTAL1-4_SM: Mfr_Name: Abracon; Mfr_Part_Number: ABM8G-12.000MHZ-B4Y-T
Z_SH-H1 Z_SH-H2 = SHUNT-3PINHEADER
Z_SH-J1 Z_SH-J2 = SHUNT-JUMPER-0603

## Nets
0.9V: U5.AE25(VREFB2AN0) U5.AG14(VREFB4AN0) U5.AG20(VREFB3AN0) U5.AH19(VREFB3CN0) U5.AJ16(VREFB4CN0) ; also on sheet 16 18 20
0.9V_DDR: CN1.1 CN1.2 CN1.3 CN1.4 CN4.1 CN4.2 CN4.3 CN4.4 CN7.1 CN7.2 CN7.3 CN7.4 CN10.1 CN10.2 CN10.3 CN10.4 RN8.1 RN8.2 RN8.3 RN8.4 RN9.1 RN9.2 RN9.3 RN9.4 RN12.1 RN12.2 RN12.3 RN12.4 RN13.1 RN13.2 RN13.3 RN13.4 RN18.1 RN18.2 RN18.3 RN18.4 RN19.1 RN19.2 RN19.3 RN19.4 RN24.1 RN24.2 RN24.3 RN24.4 ; also on sheet 16
0.9V_VREF: C34.1 J6.1(VREF) ; also on sheet 16
1.8V: C22.1 C23.1 C24.1 C25.1 C26.1 C27.1 C28.1 C29.1 C30.1 C31.1 C32.1 C33.1 C35.1 C36.1 C37.1 C38.1 C39.1 J6.81(VDD) J6.82(VDD) J6.87(VDD) J6.88(VDD) J6.95(VDD) J6.96(VDD) J6.103(VDD) J6.104(VDD) J6.111(VDD) J6.112(VDD) J6.117(VDD) J6.118(VDD) J6.199(VDDSPD) JP3.1(Pin1) JP4.1(Pin1) R9.1 R10.1 ; also on sheet 9 16 18 20
1.8V_USB: C3.1 C4.1 C13.1 C14.1 C15.1 U3.12(VCORE) U3.37(VCORE) U3.49(VREGOUT) U3.64(VCORE)
3.0V: JP3.3(Pin3) JP4.3(Pin3) ; also on sheet 17 18 20 21
3.3V: C45.1 L4.1 R15.1 R68.1 R69.1 R70.1 R71.1 R72.1 R73.1 R74.1 R75.1 R80.1 R81.1 R82.1 R83.1 R84.1 R85.1 R86.1 R87.1 R88.1 Y2.1(EN) Y2.4(VCC) ; also on sheet 17 18
3.3V_CLKB: C40.1 C41.1 L4.2 U6.1(VCC)
3.3V_USB: C7.1 C9.1 C16.1 C17.1 C18.1 C19.1 FB1.1 FB2.1 R5.1 R6.1 R7.1 U2.5(OUT) U3.20(VCCIO) U3.31(VCCIO) U3.42(VCCIO) U3.50(VREGIN) U3.56(VCCIO) U4.6(ORG) U4.8(VCC) U16.19(Vccb) U17.19(Vccb)
5V_IN: C349.1 C350.1 R77.1 R79.1 R154.2 R155.2 U1.8(VCC) U14.8(VCC) ; also on sheet 16 17 18
5V_USB: C8.1 L3.2 U2.1(IN)
6.0V_OUT: F2.1 ; also on sheet 17
GND: C1.2 C2.2 C3.2 C4.2 C5.2 C6.2 C7.2 C8.2 C9.2 C10.2 C11.2 C12.2 C13.2 C14.2 C15.2 C16.2 C17.2 C18.2 C19.2 C20.2 C21.2 C22.2 C23.2 C24.2 C25.2 C26.2 C27.2 C28.2 C29.2 C30.2 C31.2 C32.2 C33.2 C34.2 C35.2 C36.2 C37.2 C38.2 C39.2 C40.2 C41.2 C45.2 C338.2 C339.2 C340.2 C341.2 C342.2 C349.2 C350.2 CN1.5 CN1.6 CN1.7 CN1.8 CN4.5 CN4.6 CN4.7 CN4.8 CN7.5 CN7.6 CN7.7 CN7.8 CN10.5 CN10.6 CN10.7 CN10.8 D1.2(CATHODE) D10.2(CATHODE) J1.2 J1.4 J1.6 J1.8 J1.10 J1.12 J1.14 J1.16 J1.18 J1.20 J1.22 J1.24 J1.26 J1.28 J1.30 J1.32 J1.34 J1.36 J1.38 J1.40 J1.42 J1.44 J1.46 J1.48 J1.50 J1.52 J1.54 J1.56 J1.58 J1.60 J1.62 J1.64 J1.66 J1.68 J1.70 J1.72 J1.74 J1.76 J1.78 J1.80 J1.82 J1.84 J1.86 J1.88 J2.1 J2.2 J2.7 J2.8 J2.13 J2.14 J2.19 J2.20 J2.25 J2.26 J2.31 J2.32 J2.37 J2.38 J2.43 J2.44 J2.49 J2.50 J2.55 J2.56 J2.61(GND) J2.62(GND) J2.63(GND) J2.64(GND) J3.5 J3.6 J3.11 J3.12 J3.17 J3.18 J3.23 J3.24 J3.29 J3.30 J3.35 J3.36 J3.41 J3.42 J3.47 J3.48 J3.53 J3.54 J3.59 J3.60 J3.61 J3.62 J3.67 J3.68 J3.73 J3.74 J3.79 J3.80 J3.85 J3.86 J3.91 J3.92 J3.97 J3.98 J3.103 J3.104 J3.110 J3.116 J3.121(GND) J3.122(GND) J3.123(GND) J3.124(GND) J3.125(GND) J3.126(GND) J3.127(GND) J3.128(GND) J4.7 J4.8 J4.9 J4.10 J4.65 J4.66 J4.71 J4.72 J4.77 J4.78 J4.83 J4.84 J4.89 J4.90 J4.95 J4.96 J4.101 J4.102 J4.107 J4.108 J4.113 J4.114 J4.119 J4.120 J4.125 J4.126 J4.131 J4.132 J4.137 J4.138 J4.143 J4.144 J4.149 J4.150 J4.155 J4.156 J4.161 J4.162 J4.167 J4.168 J4.173 J4.174 J4.179 J4.180 J4.181(GND) J4.182(GND) J4.183(GND) J4.184(GND) J4.185(GND) J4.186(GND) J4.187(GND) J4.188(GND) J4.189(GND) J4.190(GND) J4.191(GND) J4.192(GND) J5.5(GND) J5.6(GND1) J5.7(GND2) J5.8(GND3) J5.9(GND4) J6.2(VSS) J6.3(VSS) J6.8(VSS) J6.9(VSS) J6.12(VSS) J6.15(VSS) J6.18(VSS) J6.21(VSS) J6.24(VSS) J6.27(VSS) J6.28(VSS) J6.33(VSS) J6.34(VSS) J6.39(VSS) J6.40(VSS) J6.41(VSS) J6.42(VSS) J6.47(VSS) J6.48(VSS) J6.53(VSS) J6.54(VSS) J6.59(VSS) J6.60(VSS) J6.65(VSS) J6.66(VSS) J6.71(VSS) J6.72(VSS) J6.77(VSS) J6.78(VSS) J6.121(VSS) J6.122(VSS) J6.127(VSS) J6.128(VSS) J6.132(VSS) J6.133(VSS) J6.138(VSS) J6.139(VSS) J6.144(VSS) J6.145(VSS) J6.149(VSS) J6.150(VSS) J6.155(VSS) J6.156(VSS) J6.161(VSS) J6.162(VSS) J6.165(VSS) J6.168(VSS) J6.171(VSS) J6.172(VSS) J6.177(VSS) J6.178(VSS) J6.183(VSS) J6.184(VSS) J6.187(VSS) J6.190(VSS) J6.193(VSS) J6.196(VSS) J6.198(SA0) J6.200(SA1) J7.2(GND) J7.3(GND) J7.4(GND) J7.5(GND) J18.2 R4.2 R16.2 R45.2 R89.1 R90.1 R91.2 R92.2 R93.2 R94.2 R116.1 SJP1.3(Pin3) SJP2.3(Pin3) SW1.1(A1) SW1.2(A2) SW1.3(A3) SW1.4(A4) SW2.1 SW2.2 SW3.1 SW3.2 SW4.1 SW4.2 SW5.1 SW5.2 SW6.1 SW6.2 SW7.3 SW7.6 SW7.9 SW7.12 TP22.1(TP) TP23.1(TP) TP24.1(TP) TP25.1(TP) TP26.1(TP) TP27.1(TP) U1.4(GND) U2.2(GND) U2.3(~{EN}) U3.1(GND) U3.5(GND) U3.10(AGND) U3.11(GND) U3.13(TEST) U3.15(GND) U3.25(GND) U3.35(GND) U3.47(GND) U3.51(GND) U4.5(GND) U4.7(NC) U5.AB25(VREFB2CN0) U5.AC9(VREFB5CN0) U5.AF8(VREFB5AN0) U5.AK1(RREF_R0) U5.D1(RREF_R1) U5.F16(VREFB7CN0) U5.G14(VREFB7AN0) U5.G19(VREFB8CN0) U5.H20(VREFB8AN0) U5.K9(VREFB6AN0) U5.M21(NC) U5.M22(NC) U5.M25(VREFB1AN0) U5.R9(VREFB6CN0) U5.R26(VREFB1CN0) U6.2(GND) U14.4(GND) U16.11(GND) U17.11(GND) Y1.2 Y1.4 Y2.2(GND) ; also on sheet 9 14 15 16 17 18 19 20 21
ADBUS0: TP1.1 U3.16(ADBUS0) ; also on sheet 15
ADBUS1: TP2.1 U3.17(ADBUS1) ; also on sheet 15
ADBUS2: TP3.1 U3.18(ADBUS2) ; also on sheet 15
ADBUS3: TP4.1 U3.19(ADBUS3) ; also on sheet 15
ADC_0: U3.24(ADBUS7) U16.20(B1)
ADC_1: U3.21(ADBUS4) U16.18(B2)
ADC_2: U3.22(ADBUS5) U16.17(B3)
ADC_3: U3.23(ADBUS6) U16.16(B4)
ADC_4: U3.30(BDBUS4) U16.15(B5)
ADC_5: U3.32(BDBUS5) U16.14(B6)
ADC_6: U3.33(BDBUS6) U16.13(B7)
ADC_7: U3.34(BDBUS7) U16.12(B8)
ADC_GPIO_0: JP5.2 U16.1(A1)
ADC_GPIO_1: JP6.2 U16.3(A2)
ADC_GPIO_2: JP7.2 U16.4(A3)
ADC_GPIO_3: J3.111 U16.5(A4)
ADC_GPIO_4: J3.113 U16.6(A5)
ADC_GPIO_5: J3.115 U16.7(A6)
ADC_GPIO_6: J3.117 U16.8(A7)
ADC_GPIO_7: J3.119 U16.9(A8)
BDBUS0: TP5.1 U3.26(BDBUS0) ; also on sheet 15
BDBUS1: TP6.1 U3.27(BDBUS1) ; also on sheet 15
BDBUS2: TP7.1 U3.28(BDBUS2) ; also on sheet 15
BDBUS3: TP8.1 U3.29(BDBUS3) ; also on sheet 15
CDBUS0: TP9.1 U3.38(CDBUS0) ; also on sheet 15
CDBUS1: TP10.1 U3.39(CDBUS1) ; also on sheet 15
CDBUS2: TP11.1 U3.40(CDBUS2) ; also on sheet 15
CDBUS3: TP12.1 U3.41(CDBUS3) ; also on sheet 15
CLK_GXB1_M: J2.54 U5.AD34(REFCLK_L0N,_GXB_CMURX_L0N)
CLK_GXB1_P: J2.52 U5.AD33(REFCLK_L0P,_GXB_CMURX_L0P)
CLK_GXB2_M: J2.60 U5.AB34(REFCLK_L1N,_GXB_CMURX_L1N)
CLK_GXB2_P: J2.58 U5.AB33(REFCLK_L1P,_GXB_CMURX_L1P)
CLK_GXB3_M: J2.53 U5.M34(REFCLK_L2N,_GXB_CMURX_L2N)
CLK_GXB3_P: J2.51 U5.M33(REFCLK_L2P,_GXB_CMURX_L2P)
CLK_GXB4_M: J2.59 U5.K34(REFCLK_L3N,_GXB_CMURX_L3N)
CLK_GXB4_P: J2.57 U5.K33(REFCLK_L3P,_GXB_CMURX_L3P)
CLK_OSCN: R76.1 U5.AP20(CLK5N_DIFFOUT_B31N) U6.4(Y)
CLK_OSCP: R76.2 U5.AN20(CLK5P_DIFFOUT_B31P) U6.3(Z)
CMOS_CLK: C46.2 R15.2 R16.1 U5.B18(CLK14P_DIFFIO_RX_T17P_DIFFOUT_T33P)
CMOS_PORT0_0: J1.1 U5.B15(CLK12P_DIFFIO_RX_T16P_DIFFOUT_T32P)
CMOS_PORT0_1: J1.3 ; also on sheet 15
CMOS_PORT0_2: J1.5 ; also on sheet 15
CMOS_PORT0_3: J1.7 ; also on sheet 15
CMOS_PORT0_4: J1.9 ; also on sheet 15
CMOS_PORT0_5: J1.11 ; also on sheet 15
CMOS_PORT0_6: J1.13 ; also on sheet 15
CMOS_PORT0_7: J1.15 ; also on sheet 15
CMOS_PORT0_8: J1.17 ; also on sheet 15
CMOS_PORT0_9: J1.19 ; also on sheet 15
CMOS_PORT0_10: J1.21 ; also on sheet 15
CMOS_PORT0_11: J1.23 ; also on sheet 15
CMOS_PORT0_12: J1.25 ; also on sheet 15
CMOS_PORT0_13: J1.27 ; also on sheet 15
CMOS_PORT0_14: J1.29 ; also on sheet 15
CMOS_PORT0_15: J1.31 ; also on sheet 15
CMOS_PORT0_16: J1.33 ; also on sheet 15
CMOS_PORT0_17: J1.35 ; also on sheet 15
CMOS_PORT0_18: J1.37 ; also on sheet 15
CMOS_PORT0_19: J1.39 ; also on sheet 15
CMOS_PORT0_20: J1.41 ; also on sheet 15
CMOS_PORT0_21: J1.43 ; also on sheet 15
CMOS_PORT1_0: J1.45 U5.B20(CLK15P_DIFFOUT_T34P)
CMOS_PORT1_1: J1.47 ; also on sheet 14
CMOS_PORT1_2: J1.49 ; also on sheet 14
CMOS_PORT1_3: J1.51 ; also on sheet 14
CMOS_PORT1_4: J1.53 ; also on sheet 14
CMOS_PORT1_5: J1.55 ; also on sheet 14
CMOS_PORT1_6: J1.57 ; also on sheet 14
CMOS_PORT1_7: J1.59 ; also on sheet 14
CMOS_PORT1_8: J1.61 ; also on sheet 14
CMOS_PORT1_9: J1.63 ; also on sheet 14
CMOS_PORT1_10: J1.65 ; also on sheet 14
CMOS_PORT1_11: J1.67 ; also on sheet 14
CMOS_PORT1_12: J1.69 ; also on sheet 14
CMOS_PORT1_13: J1.71 ; also on sheet 14
CMOS_PORT1_14: J1.73 ; also on sheet 14
CMOS_PORT1_15: J1.75 ; also on sheet 14
CMOS_PORT1_16: J1.77 ; also on sheet 14
CMOS_PORT1_17: J1.79 ; also on sheet 14
CMOS_PORT1_18: J1.81 ; also on sheet 14
CMOS_PORT1_19: J1.83 ; also on sheet 14
CMOS_PORT1_20: J1.85 ; also on sheet 15
CMOS_PORT1_21: J1.87 ; also on sheet 15
CMOS_SP1: J4.26 ; also on sheet 14
CMOS_SP2: J4.28 ; also on sheet 14
CMOS_SP3: J4.38 ; also on sheet 14
CMOS_SP4: J4.40 ; also on sheet 14
CMOS_SP5: J4.46 ; also on sheet 14
CMOS_SP6: J4.50 ; also on sheet 14
CMOS_SP7: J4.52 ; also on sheet 14
CPU_RESET: R103.1 U5.A17(CLK13N_DIFFOUT_T31N)
DA0N: J4.165 ; also on sheet 9
DA0P: J4.163 ; also on sheet 9
DA1N: J4.159 ; also on sheet 9
DA1P: J4.157 ; also on sheet 9
DA2N: J4.153 ; also on sheet 9
DA2P: J4.151 ; also on sheet 9
DA3N: J4.147 ; also on sheet 9
DA3P: J4.145 ; also on sheet 9
DA4N: J4.141 ; also on sheet 9
DA4P: J4.139 ; also on sheet 9
DA5N: J4.135 ; also on sheet 9
DA5P: J4.133 ; also on sheet 9
DA6N: J4.129 U5.U25(IO_1C_U25/DQ6L/DIFFIO_TX_L12N/DIFFOUT_L23N/DATA4)
DA6P: J4.127 U5.T24(IO_1C_T24/DQ6L/DIFFIO_TX_L12P/DIFFOUT_L23P/DATA5)
DA7N: J4.123 U5.R24(IO_1C_R24/DQ7L/DIFFIO_TX_L13N/DIFFOUT_L25N/INIT_DONE)
DA7P: J4.121 U5.R23(IO_1C_R23/DQ7L/DIFFIO_TX_L13P/DIFFOUT_L25P/CRC_ERROR)
DA8N: J4.111 U5.J27(IO_1A_J27/DQ4L/DIFFIO_TX_L7N/DIFFOUT_L13N)
DA8P: J4.109 U5.H26(IO_1A_H26/DQ4L/DIFFIO_TX_L7P/DIFFOUT_L13P)
DA9N: J4.105 U5.P24(IO_1A_P24/DQ3L/DIFFIO_TX_L5N/DIFFOUT_L9N)
DA9P: J4.103 U5.P23(IO_1A_P23/DQ3L/DIFFIO_TX_L5P/DIFFOUT_L9P)
DA10N: J4.99 U5.N26(IO_1C_N26/DIFFIO_TX_L9N/DIFFOUT_L17N)
DA10P: J4.97 U5.N25(IO_1C_N25/DIFFIO_TX_L9P/DIFFOUT_L17P)
DA11N: J4.93 U5.M24(IO_1A_M24/DIFFIO_TX_L8N/DIFFOUT_L15N)
DA11P: J4.91 U5.N23(IO_1A_N23/DIFFIO_TX_L8P/DIFFOUT_L15P)
DA12N: J4.87 U5.N27(IO_1C_N27/DQ5L/DIFFIO_TX_L10N/DIFFOUT_L19N/CLKUSR)
DA12P: J4.85 U5.M26(IO_1C_M26/DQ5L/DIFFIO_TX_L10P/DIFFOUT_L19P)
DA13N: J4.81 U5.K27(IO_1A_K27/DQ2L/DIFFIO_TX_L4N/DIFFOUT_L7N)
DA13P: J4.79 U5.K26(IO_1A_K26/DQ2L/DIFFIO_TX_L4P/DIFFOUT_L7P)
DA14N: J4.75 U5.L23(IO_1A_L23/DQ1L/DIFFIO_TX_L2N/DIFFOUT_L3N)
DA14P: J4.73 U5.M23(IO_1A_M23/DQ1L/DIFFIO_TX_L2P/DIFFOUT_L3P)
DA15N: J4.69 U5.K24(IO_1A_K24/DIFFIO_TX_L1N/DIFFOUT_L1N)
DA15P: J4.67 U5.L24(IO_1A_L24/DIFFIO_TX_L1P/DIFFOUT_L1P)
DAC_0: U3.46(CDBUS7) U17.20(B1)
DAC_1: U3.43(CDBUS4) U17.18(B2)
DAC_2: U3.44(CDBUS5) U17.17(B3)
DAC_3: U3.45(CDBUS6) U17.16(B4)
DAC_4: U3.55(DDBUS4) U17.15(B5)
DAC_5: U3.57(DDBUS5) U17.14(B6)
DAC_6: U17.13(B7) ; also on sheet 14
DAC_7: U17.12(B8) ; also on sheet 14
DAC_GPIO_0: J4.45 U17.1(A1)
DAC_GPIO_1: J4.47 U17.3(A2)
DAC_GPIO_2: J4.49 U17.4(A3)
DAC_GPIO_3: J4.51 U17.5(A4)
DAC_GPIO_4: J4.53 U17.6(A5)
DAC_GPIO_5: J4.55 U17.7(A6)
DAC_GPIO_6: J4.57 U17.8(A7)
DAC_GPIO_7: J4.59 U17.9(A8)
DACLKN: J4.117 U5.M29(IO_1C_M29/PLL_L2_CLKOUT0N/DIFFIO_TX_L14N/DIFFOUT_L27N)
DACLKP: J4.115 U5.M28(IO_1C_M28/PLL_L2_FB_CLKOUT0P/DIFFIO_TX_L14P/DIFFOUT_L27P)
DB0N: J4.166 ; also on sheet 12
DB0P: J4.164 ; also on sheet 12
DB1N: J4.160 ; also on sheet 12
DB1P: J4.158 ; also on sheet 12
DB2N: J4.154 ; also on sheet 12
DB2P: J4.152 ; also on sheet 12
DB3N: J4.148 ; also on sheet 12
DB3P: J4.146 ; also on sheet 12
DB4N: J4.142 ; also on sheet 12
DB4P: J4.140 ; also on sheet 12
DB5N: J4.136 ; also on sheet 12
DB5P: J4.134 ; also on sheet 12
DB6N: J4.130 ; also on sheet 12
DB6P: J4.128 ; also on sheet 12
DB7N: J4.124 ; also on sheet 12
DB7P: J4.122 ; also on sheet 12
DB8N: J4.112 ; also on sheet 12
DB8P: J4.110 ; also on sheet 12
DB9N: J4.106 ; also on sheet 12
DB9P: J4.104 ; also on sheet 12
DB10N: J4.100 ; also on sheet 12
DB10P: J4.98 ; also on sheet 12
DB11N: J4.94 ; also on sheet 12
DB11P: J4.92 ; also on sheet 12
DB12N: J4.88 ; also on sheet 12
DB12P: J4.86 ; also on sheet 12
DB13N: J4.82 ; also on sheet 12
DB13P: J4.80 ; also on sheet 12
DB14N: J4.76 ; also on sheet 13
DB14P: J4.74 ; also on sheet 13
DB15N: J4.70 ; also on sheet 13
DB15P: J4.68 ; also on sheet 13
DBCLKN: J4.39 ; also on sheet 13
DBCLKP: J4.37 ; also on sheet 13
DCLK_M: J3.56 R54.1 U5.AA6(CLK8N)
DCLK_P: J3.58 R54.2 U5.AA7(CLK8P)
DDR2_A0: J6.102(A0) RN12.6 ; also on sheet 9
DDR2_A1: J6.101(A1) RN13.7 ; also on sheet 9
DDR2_A2: J6.100(A2) RN13.8 ; also on sheet 9
DDR2_A3: J6.99(A3) RN13.5 ; also on sheet 9
DDR2_A4: J6.98(A4) RN13.6 ; also on sheet 9
DDR2_A5: J6.97(A5) RN18.7 ; also on sheet 9
DDR2_A6: J6.94(A6) RN18.8 ; also on sheet 9
DDR2_A7: J6.92(A7) RN18.6 ; also on sheet 9
DDR2_A8: J6.93(A8) RN18.5 ; also on sheet 9
DDR2_A9: J6.91(A9) RN19.7 ; also on sheet 9
DDR2_A10: J6.105(A10/AP) RN12.5 ; also on sheet 9
DDR2_A11: J6.90(A11) RN19.8 ; also on sheet 9
DDR2_A12: J6.89(A12) RN19.5 ; also on sheet 9
DDR2_A13: J6.116(A13) RN8.8 ; also on sheet 9
DDR2_A14: J6.86(A14) RN19.6 ; also on sheet 9
DDR2_A15: J6.84(A15) RN24.7 ; also on sheet 9
DDR2_BA0: J6.107(BA0) RN12.7 ; also on sheet 11
DDR2_BA1: J6.106(BA1) RN12.8 ; also on sheet 11
DDR2_BA2: J6.85(BA2) RN24.8 ; also on sheet 11
DDR2_CAS_n: J6.113(~{CAS}) RN9.7 ; also on sheet 11
DDR2_CKE0: J6.79(CKE0) RN24.6 ; also on sheet 11
DDR2_CKE1: J6.80(CKE1) RN24.5 ; also on sheet 10
DDR2_CLK_n0: J6.32(~{CK}0) ; also on sheet 11
DDR2_CLK_n1: J6.166(~{CK}1) ; also on sheet 11
DDR2_CLK_p0: J6.30(CK0) ; also on sheet 11
DDR2_CLK_p1: J6.164(CK1) ; also on sheet 11
DDR2_CS_n0: J6.110(~{S}0) RN9.8 ; also on sheet 11
DDR2_CS_n1: J6.115(~{S}1) RN8.7 ; also on sheet 10
DDR2_DM0: J6.10(DM0) ; also on sheet 11
DDR2_DM1: J6.26(DM1) ; also on sheet 11
DDR2_DM2: J6.52(DM2) ; also on sheet 10
DDR2_DM3: J6.67(DM3) ; also on sheet 11
DDR2_DM4: J6.130(DM4) ; also on sheet 10
DDR2_DM5: J6.147(DM5) ; also on sheet 10
DDR2_DM6: J6.170(DM6) ; also on sheet 11
DDR2_DM7: J6.185(DM7) ; also on sheet 10
DDR2_DQ0: J6.5(DQ0) ; also on sheet 11
DDR2_DQ1: J6.7(DQ1) ; also on sheet 11
DDR2_DQ2: J6.17(DQ2) ; also on sheet 11
DDR2_DQ3: J6.19(DQ3) ; also on sheet 11
DDR2_DQ4: J6.4(DQ4) ; also on sheet 11
DDR2_DQ5: J6.6(DQ5) ; also on sheet 11
DDR2_DQ6: J6.14(DQ6) ; also on sheet 11
DDR2_DQ7: J6.16(DQ7) ; also on sheet 11
DDR2_DQ8: J6.23(DQ8) ; also on sheet 11
DDR2_DQ9: J6.25(DQ9) ; also on sheet 11
DDR2_DQ10: J6.35(DQ10) ; also on sheet 11
DDR2_DQ11: J6.37(DQ11) ; also on sheet 11
DDR2_DQ12: J6.20(DQ12) ; also on sheet 11
DDR2_DQ13: J6.22(DQ13) ; also on sheet 11
DDR2_DQ14: J6.36(DQ14) ; also on sheet 11
DDR2_DQ15: J6.38(DQ15) ; also on sheet 11
DDR2_DQ16: J6.43(DQ16) ; also on sheet 10
DDR2_DQ17: J6.45(DQ17) ; also on sheet 10
DDR2_DQ18: J6.55(DQ18) ; also on sheet 10
DDR2_DQ19: J6.57(DQ19) ; also on sheet 10
DDR2_DQ20: J6.44(DQ20) ; also on sheet 10
DDR2_DQ21: J6.46(DQ21) ; also on sheet 10
DDR2_DQ22: J6.56(DQ22) ; also on sheet 10
DDR2_DQ23: J6.58(DQ23) ; also on sheet 10
DDR2_DQ24: J6.61(DQ24) ; also on sheet 11
DDR2_DQ25: J6.63(DQ25) ; also on sheet 11
DDR2_DQ26: J6.73(DQ26) ; also on sheet 11
DDR2_DQ27: J6.75(DQ27) ; also on sheet 11
DDR2_DQ28: J6.62(DQ28) ; also on sheet 11
DDR2_DQ29: J6.64(DQ29) ; also on sheet 11
DDR2_DQ30: J6.74(DQ30) ; also on sheet 11
DDR2_DQ31: J6.76(DQ31) ; also on sheet 11
DDR2_DQ32: J6.123(DQ32) ; also on sheet 10
DDR2_DQ33: J6.125(DQ33) ; also on sheet 10
DDR2_DQ34: J6.135(DQ34) ; also on sheet 10
DDR2_DQ35: J6.137(DQ35) ; also on sheet 10
DDR2_DQ36: J6.124(DQ36) ; also on sheet 10
DDR2_DQ37: J6.126(DQ37) ; also on sheet 10
DDR2_DQ38: J6.134(DQ38) ; also on sheet 10
DDR2_DQ39: J6.136(DQ39) ; also on sheet 10
DDR2_DQ40: J6.141(DQ40) ; also on sheet 10
DDR2_DQ41: J6.143(DQ41) ; also on sheet 10
DDR2_DQ42: J6.151(DQ42) ; also on sheet 10
DDR2_DQ43: J6.153(DQ43) ; also on sheet 10
DDR2_DQ44: J6.140(DQ44) ; also on sheet 10
DDR2_DQ45: J6.142(DQ45) ; also on sheet 10
DDR2_DQ46: J6.152(DQ46) ; also on sheet 10
DDR2_DQ47: J6.154(DQ47) ; also on sheet 10
DDR2_DQ48: J6.157(DQ48) ; also on sheet 11
DDR2_DQ49: J6.159(DQ49) ; also on sheet 11
DDR2_DQ50: J6.173(DQ50) ; also on sheet 11
DDR2_DQ51: J6.175(DQ51) ; also on sheet 11
DDR2_DQ52: J6.158(DQ52) ; also on sheet 11
DDR2_DQ53: J6.160(DQ53) ; also on sheet 11
DDR2_DQ54: J6.174(DQ54) ; also on sheet 11
DDR2_DQ55: J6.176(DQ55) ; also on sheet 11
DDR2_DQ56: J6.179(DQ56) ; also on sheet 10
DDR2_DQ57: J6.181(DQ57) ; also on sheet 10
DDR2_DQ58: J6.189(DQ58) ; also on sheet 10
DDR2_DQ59: J6.191(DQ59) ; also on sheet 10
DDR2_DQ60: J6.180(DQ60) ; also on sheet 10
DDR2_DQ61: J6.182(DQ61) ; also on sheet 10
DDR2_DQ62: J6.192(DQ62) ; also on sheet 10
DDR2_DQ63: J6.194(DQ63) ; also on sheet 10
DDR2_DQS0: J6.13(DQS0) ; also on sheet 11
DDR2_DQS1: J6.31(DQS1) ; also on sheet 11
DDR2_DQS2: J6.51(DQS2) ; also on sheet 10
DDR2_DQS3: J6.70(DQS3) ; also on sheet 11
DDR2_DQS4: J6.131(DQS4) ; also on sheet 10
DDR2_DQS5: J6.148(DQS5) ; also on sheet 10
DDR2_DQS6: J6.169(DQS6) ; also on sheet 11
DDR2_DQS7: J6.188(DQS7) ; also on sheet 10
DDR2_DQSn0: J6.11(~{DQS}0) ; also on sheet 11
DDR2_DQSn1: J6.29(~{DQS}1) ; also on sheet 11
DDR2_DQSn2: J6.49(~{DQS}2) ; also on sheet 10
DDR2_DQSn3: J6.68(~{DQS}3) ; also on sheet 11
DDR2_DQSn4: J6.129(~{DQS}4) ; also on sheet 10
DDR2_DQSn5: J6.146(~{DQS}5) ; also on sheet 10
DDR2_DQSn6: J6.167(~{DQS}6) ; also on sheet 11
DDR2_DQSn7: J6.186(~{DQS}7) ; also on sheet 10
DDR2_ODT0: J6.114(ODT0) RN8.6 ; also on sheet 11
DDR2_ODT1: J6.119(ODT1) RN8.5 ; also on sheet 10
DDR2_RAS_n: J6.108(~{RAS}) RN9.6 ; also on sheet 11
DDR2_SCL: J6.197(SCL) R10.2
DDR2_SDA: J6.195(SDA) R9.2
DDR2_WE_n: J6.109(~{WE}) RN9.5 ; also on sheet 11
DM: C12.1 R1.2 U3.7(DM)
DP: C11.1 R2.2 U3.8(DP)
DS3N: J4.22 ; also on sheet 13
DS3P: J4.20 ; also on sheet 13
DS5N: J4.34 ; also on sheet 13
DS5P: J4.32 ; also on sheet 13
EEDATA: R8.1 U3.61(EEDATA) U4.3(DI)
EN1: U14.7(1Y) ; also on sheet 16 17
EN2: U1.7(1Y) ; also on sheet 16
EN3: U1.5(2Y) ; also on sheet 16
EN4: U1.2(3Y) ; also on sheet 16
EN5: U14.5(2Y) ; also on sheet 17
EN6: U14.2(3Y) ; also on sheet 18
FCLK_M: J3.64 U5.AC6(CLK9N_DIFFIO_RX_R14N_DIFFOUT_R28N)
FCLK_P: J3.66 U5.AB6(CLK9P_DIFFIO_RX_R14P_DIFFOUT_R28P)
FPGA_CLK2_N: C293.2 J4.33
FPGA_CLK2_P: C292.2 J4.31
FPGA_CLKN: C264.2 J4.118
FPGA_CLKP: C291.2 J4.116
FPGA_CONF_DONE: R67.2 ; also on sheet 21
FPGACLK2N: C293.1 R105.2 U5.N6(CLK10N)
FPGACLK2P: C292.1 R105.1 U5.N7(CLK10P)
FPGACLKN: C264.1 R104.1 U5.N29(CLK1N)
FPGACLKP: C291.1 R104.2 U5.N28(CLK1P)
FTDI_BLAST_TDI: U3.52(DDBUS1) ; also on sheet 21
FTDI_BLAST_TDO: U3.53(DDBUS2) ; also on sheet 21
FTDI_NCE: U3.58(DDBUS6) ; also on sheet 21
FTDI_nCONFIG: U3.59(DDBUS7) ; also on sheet 21
FTDI_TCK: U3.48(DDBUS0) ; also on sheet 21
FTDI_TMS: U3.54(DDBUS3) ; also on sheet 21
GXB_RX0M: J2.3 U5.AH34(GXB_RX_L0N)
GXB_RX0P: J2.5 U5.AH33(GXB_RX_L0P)
GXB_RX1M: J2.9 U5.AF34(GXB_RX_L1N)
GXB_RX1P: J2.11 U5.AF33(GXB_RX_L1P)
GXB_RX2M: J2.15 U5.Y34(GXB_RX_L2N)
GXB_RX2P: J2.17 U5.Y33(GXB_RX_L2P)
GXB_RX3M: J2.21 U5.V34(GXB_RX_L3N)
GXB_RX3P: J2.23 U5.V33(GXB_RX_L3P)
GXB_RX4M: J2.27 U5.T34(GXB_RX_L4N)
GXB_RX4P: J2.29 U5.T33(GXB_RX_L4P)
GXB_RX5M: J2.33 U5.P34(GXB_RX_L5N)
GXB_RX5P: J2.35 U5.P33(GXB_RX_L5P)
GXB_RX6M: J2.39 U5.H34(GXB_RX_L6N)
GXB_RX6P: J2.41 U5.H33(GXB_RX_L6P)
GXB_RX7M: J2.45 U5.F34(GXB_RX_L7N)
GXB_RX7P: J2.47 U5.F33(GXB_RX_L7P)
GXB_TX0M: J2.4 U5.AG32(GXB_TX_L0N)
GXB_TX0P: J2.6 U5.AG31(GXB_TX_L0P)
GXB_TX1M: J2.10 U5.AE32(GXB_TX_L1N)
GXB_TX1P: J2.12 U5.AE31(GXB_TX_L1P)
GXB_TX2M: J2.16 U5.W32(GXB_TX_L2N)
GXB_TX2P: J2.18 U5.W31(GXB_TX_L2P)
GXB_TX3M: J2.22 U5.U32(GXB_TX_L3N)
GXB_TX3P: J2.24 U5.U31(GXB_TX_L3P)
GXB_TX4M: J2.28 U5.R32(GXB_TX_L4N)
GXB_TX4P: J2.30 U5.R31(GXB_TX_L4P)
GXB_TX5M: J2.34 U5.N32(GXB_TX_L5N)
GXB_TX5P: J2.36 U5.N31(GXB_TX_L5P)
GXB_TX6M: J2.40 U5.G32(GXB_TX_L6N)
GXB_TX6P: J2.42 U5.G31(GXB_TX_L6P)
GXB_TX7M: J2.46 U5.E32(GXB_TX_L7N)
GXB_TX7P: J2.48 U5.E31(GXB_TX_L7P)
Input0_M: J3.2 ; also on sheet 9
Input0_P: J3.4 ; also on sheet 9
Input1_M: J3.8 ; also on sheet 9
Input1_P: J3.10 ; also on sheet 9
Input2_M: J3.14 ; also on sheet 12
Input2_P: J3.16 ; also on sheet 12
Input3_M: J3.20 ; also on sheet 12
Input3_P: J3.22 ; also on sheet 12
Input4_M: J3.26 ; also on sheet 12
Input4_P: J3.28 ; also on sheet 12
Input5_M: J3.32 ; also on sheet 12
Input5_P: J3.34 ; also on sheet 12
Input6_M: J3.38 ; also on sheet 12
Input6_P: J3.40 ; also on sheet 12
Input7_M: J3.44 ; also on sheet 12
Input7_P: J3.46 ; also on sheet 12
Input8_M: J3.50 ; also on sheet 12
Input8_P: J3.52 ; also on sheet 12
Input9_M: J3.1 ; also on sheet 9
Input9_P: J3.3 ; also on sheet 9
Input10_M: J3.7 ; also on sheet 9
Input10_P: J3.9 ; also on sheet 9
Input11_M: J3.13 ; also on sheet 9
Input11_P: J3.15 ; also on sheet 9
Input12_M: J3.19 ; also on sheet 13
Input12_P: J3.21 ; also on sheet 13
Input13_M: J3.25 ; also on sheet 13
Input13_P: J3.27 ; also on sheet 13
Input14_M: J3.31 ; also on sheet 13
Input14_P: J3.33 ; also on sheet 13
Input15_M: J3.37 U5.M5(CLK11N_DIFFIO_RX_R15N_DIFFOUT_R29N)
Input15_P: J3.39 U5.M6(CLK11P_DIFFIO_RX_R15P_DIFFOUT_R29P)
Input16_M: J3.43 ; also on sheet 13
Input16_P: J3.45 ; also on sheet 13
Input17_M: J3.49 ; also on sheet 13
Input17_P: J3.51 ; also on sheet 13
Input18_M: J3.55 R56.2 U5.AA29(CLK3N)
Input18_P: J3.57 R56.1 U5.AA28(CLK3P)
Input19_M: J3.70 ; also on sheet 12
Input19_P: J3.72 ; also on sheet 12
Input20_M: J3.76 ; also on sheet 12
Input20_P: J3.78 ; also on sheet 12
Input21_M: J3.82 ; also on sheet 12
Input21_P: J3.84 ; also on sheet 12
Input22_M: J3.88 ; also on sheet 12
Input22_P: J3.90 ; also on sheet 12
Input23_M: J3.94 ; also on sheet 12
Input23_P: J3.96 ; also on sheet 12
Input24_M: J3.100 ; also on sheet 12
Input24_P: J3.102 ; also on sheet 12
Input25_M: J3.106 ; also on sheet 13
Input25_P: J3.108 ; also on sheet 13
Input26_M: J3.112 ; also on sheet 13
Input26_P: J3.114 ; also on sheet 13
Input27_M: J3.118 U5.M30(IO_1C_M30/DQ7L/DIFFIO_RX_L13N/DIFFOUT_L26N/DEV_OE)
Input27_P: J3.120 U5.L29(IO_1C_L29/DQ7L/DIFFIO_RX_L13P/DIFFOUT_L26P/DEV_CLRN)
Input28_M: J3.63 U5.K30(IO_1C_K30/DQSN6L/DIFFIO_RX_L11N/DIFFOUT_L22N/DATA2)
Input28_P: J3.65 U5.L30(IO_1C_L30/DQS6L/DIFFIO_RX_L11P/DIFFOUT_L22P/DATA3)
Input29_M: J3.69 ; also on sheet 13
Input29_P: J3.71 ; also on sheet 13
Input30_M: J3.75 ; also on sheet 13
Input30_P: J3.77 ; also on sheet 13
Input31_M: J3.81 ; also on sheet 13
Input31_P: J3.83 ; also on sheet 13
Input32_M: J3.87 ; also on sheet 13
Input32_P: J3.89 ; also on sheet 13
Input33_M: J3.93 ; also on sheet 13
Input33_P: J3.95 ; also on sheet 13
Input34_M: J3.99 ; also on sheet 13
Input34_P: J3.101 ; also on sheet 13
ISTROBE_N: J4.178 U5.J25(IO_1A_J25/DQ3L/DIFFIO_TX_L6N/DIFFOUT_L11N)
ISTROBE_P: J4.176 U5.H24(IO_1A_H24/DQ3L/DIFFIO_TX_L6P/DIFFOUT_L11P)
nCS: R99.1 ; also on sheet 21
OSTROBE_N: J4.171 ; also on sheet 13
OSTROBE_P: J4.169 ; also on sheet 13
PARITY_N: J4.172 ; also on sheet 21
PARITY_P: J4.170 ; also on sheet 21
PRESENT: J4.21 ; also on sheet 14
PUSHBUTTON1: R100.1 ; also on sheet 15
PUSHBUTTON2: R101.1 ; also on sheet 15
PUSHBUTTON3: R102.1 ; also on sheet 15
SYNCA_N: J4.177 U5.J26(IO_1A_J26/DQ1L/DIFFIO_TX_L3N/DIFFOUT_L5N)
SYNCA_P: J4.175 U5.K25(IO_1A_K25/DQ1L/DIFFIO_TX_L3P/DIFFOUT_L5P)
TXEN: J4.27 ; also on sheet 14
USB_EECLK: R6.2 U3.62(EECLK) U4.2(CLK)
USB_EECS: R5.2 U3.63(EECS) U4.1(CS)
USB_REF: R4.1 U3.6(REF)
USB_RST: R3.1 U3.14(RESET)
USB_VBUS: J5.1(VBUS) L3.1 R46.1
USER_DIP0: R80.2 SW1.8(B1) ; also on sheet 15
USER_DIP1: R81.2 SW1.7(B2) ; also on sheet 15
USER_DIP2: R82.2 SW1.6(B3) ; also on sheet 15
USER_DIP3: R83.2 SW1.5(B4) ; also on sheet 15
USER_LED0: D2.2(CATHODE) ; also on sheet 15
USER_LED1: D3.2(CATHODE) ; also on sheet 15
USER_LED2: D4.2(CATHODE) ; also on sheet 15
USER_LED3: D5.2(CATHODE) ; also on sheet 15
USER_LED4: D6.2(CATHODE) ; also on sheet 15
USER_LED5: D7.2(CATHODE) ; also on sheet 15
USER_LED6: D8.2(CATHODE) ; also on sheet 15
USER_LED7: D9.2(CATHODE) ; also on sheet 15
N24747082: R7.2 R8.2 U4.4(DO)
N25673570: C1.1 C2.1 FB1.2 U3.9(VPLL)
N25674940: C5.1 C6.1 FB2.2 U3.4(VPHY)
N27224376: J5.3(D+) R2.1
N27224380: J5.2(D-) R1.1
N27319544: C20.1 U3.2(OSCI) Y1.1
N27322325: C21.1 U3.3(OSCO) Y1.3
N28576814: J3.109 JP7.1
N28621539: R3.2 R45.1 R46.2
N28765295: J3.105 JP5.1
N28765297: J3.107 JP6.1
N29450409: C46.1 J7.1(CENTER)
N38382982: C10.1 U2.4(NC/FB)
N41623470: JP3.2(Pin2) SJP1.1(Pin1) U16.2(Vcca)
N41648199: JP4.2(Pin2) SJP2.1(Pin1) U17.2(Vcca)
N44148054: R90.2 U5.B3(TEMPDIODEP)
N44148055: R89.2 U5.A3(TEMPDIODEN)
N44200403: R91.1 U5.AF1(GXB_RX_R1N) U5.AF2(GXB_RX_R1P) U5.AH1(GXB_RX_R0N) U5.AH2(GXB_RX_R0P) U5.F1(GXB_RX_R7N) U5.F2(GXB_RX_R7P) U5.H1(GXB_RX_R6N) U5.H2(GXB_RX_R6P) U5.P1(GXB_RX_R5N) U5.P2(GXB_RX_R5P) U5.T1(GXB_RX_R4N) U5.T2(GXB_RX_R4P) U5.V1(GXB_RX_R3N) U5.V2(GXB_RX_R3P) U5.Y1(GXB_RX_R2N) U5.Y2(GXB_RX_R2P)
N44225882: R92.1 U5.AB1(REFCLK_R1N,_GXB_CMURX_R1N) U5.AB2(REFCLK_R1P,_GXB_CMURX_R1P) U5.AD1(REFCLK_R0N,_GXB_CMURX_R0N) U5.AD2(REFCLK_R0P,_GXB_CMURX_R0P) U5.K1(REFCLK_R3N,_GXB_CMURX_R3N) U5.K2(REFCLK_R3P,_GXB_CMURX_R3P) U5.M1(REFCLK_R2N,_GXB_CMURX_R2N) U5.M2(REFCLK_R2P,_GXB_CMURX_R2P)
N44253255: R93.1 U5.D34(RREF_L1)
N44254573: R94.1 U5.AK34(RREF_L0)
N45582695: SJP1.2(Pin2) U16.10(OE)
N45584475: SJP2.2(Pin2) U17.10(OE)
N45611700: D7.1(ANODE) R72.2
N45611745: C339.1 R85.2 R100.2 SW3.3 SW3.4
N45611776: C341.1 R87.2 R102.2 SW5.3 SW5.4
N45611858: C342.1 R88.2 R103.2 SW6.3 SW6.4
N45611860: D3.1(ANODE) R69.2
N45611894: C340.1 R86.2 R101.2 SW4.3 SW4.4
N45612012: R79.2 SW7.2 U1.1(1A) U1.3(2A) U1.6(3A)
N45612026: J18.1 SW7.8 SW7.11
N45612034: R77.2 SW7.5 U14.1(1A) U14.3(2A) U14.6(3A)
N45612058: C338.1 R84.2 R99.2 SW2.3 SW2.4
N45612265: D4.1(ANODE) R70.2
N45612267: D5.1(ANODE) R71.2
N45612353: D8.1(ANODE) R74.2
N45612355: D9.1(ANODE) R75.2
N45612432: D2.1(ANODE) R68.2
N45612555: D6.1(ANODE) R73.2
N45612557: D1.1(ANODE) R67.1
N45639686: F2.2 J4.1 J4.2 J4.3 J4.4 R65.2
N45639690: D10.1(ANODE) R65.1
N45835930: U6.5(D) Y2.3(OUT)
N45837320: J18.3 R116.2 R155.1
N45842022: R154.1 SW7.7 SW7.10

Not connected (* = marked no-connect by the designer): J4 5 6 11 12 13 14 15 16 17 18 19 23 24 25 29 30 35 36 41 42 43 44 48 54 56 58 60 61 62 63 64; J5 4(ID)*; J6 50(NC0)* 69(NC1)* 83(NC2)* 120(NC3)* 163(TEST)*; SW7 1* 4*; U3 36(SUSPEND)* 60(PWREN)*; U5 A2(NC)* A15(CLK12N_DIFFIO_RX_T16N_DIFFOUT_T32N)* A18(CLK14N_DIFFIO_RX_T17N_DIFFOUT_T33N)* A20(CLK15N_DIFFOUT_T34N)* A32(NC)* AA3(GXB_CMUTX_R1N)* AA4(GXB_CMUTX_R1P)* AA31(GXB_CMUTX_L1P)* AA32(GXB_CMUTX_L1N)* AB29(CLK2N_DIFFIO_RX_L15N_DIFFOUT_L29N)* AC3(GXB_CMUTX_R0N)* AC4(GXB_CMUTX_R0P)* AC13(NC)* AC14(NC)* AC15(NC)* AC16(NC)* AC17(NC)* AC19(NC)* AC20(NC)* AC21(NC)* AC22(NC)* AC29(CLK2P_DIFFIO_RX_L15P_DIFFOUT_L29P)* AC31(GXB_CMUTX_L0P)* AC32(GXB_CMUTX_L0N)* AD14(NC)* AD15(NC)* AD20(NC)* AD21(NC)* AE3(GXB_TX_R1N)* AE4(GXB_TX_R1P)* AE13(NC)* AE14(NC)* AE20(NC)* AE21(NC)* AE22(NC)* AF13(NC)* AG3(GXB_TX_R0N)* AG4(GXB_TX_R0P)* AJ3(NC)* AJ4(NC)* AJ31(NC)* AJ32(NC)* AK3(NC)* AK32(NC)* AL4(NC)* AL30(NC)* AL31(NC)* AM4(NC)* AM31(NC)* AM32(NC)* AN3(NC)* AN15(CLK6P_DIFFIO_RX_B17P_DIFFOUT_B33P)* AN17(CLK7P_DIFFOUT_B34P)* AN18(CLK4P_DIFFIO_RX_B16P_DIFFOUT_B32P)* AN32(NC)* AP2(NC)* AP3(NC)* AP15(CLK6N_DIFFIO_RX_B17N_DIFFOUT_B33N)* AP17(CLK7N_DIFFOUT_B34N)* AP18(CLK4N_DIFFIO_RX_B16N_DIFFOUT_B32N)* AP32(NC)* AP33(NC)* B17(CLK13P_DIFFOUT_T31P)* C4(NC)* C28(RUP1A/DIFFIO_RX_L1P/DIFFOUT_L2P)* C29(IO_1A_C29/DQS2L/DIFFIO_RX_L3P/DIFFOUT_L6P)* C30(IO_1A_C30/DQSN2L/DIFFIO_RX_L3N/DIFFOUT_L6N)* C31(NC)* D28(IO_1A_D28/DQS1L/DIFFIO_RX_L2P/DIFFOUT_L4P)* D29(RDN1A/DIFFIO_RX_L1N/DIFFOUT_L2N)* E3(GXB_TX_R7N)* E4(GXB_TX_R7P)* E26(NC)* E27(NC)* E29(IO_1A_E29/DQSN1L/DIFFIO_RX_L2N/DIFFOUT_L4N)* F26(IO_1A_F26/DQ4L/DIFFIO_RX_L7P/DIFFOUT_L14P)* F28(IO_1A_F28/DQ2L/DIFFIO_RX_L4P/DIFFOUT_L8P)* F29(IO_1A_F29/DQ2L/DIFFIO_RX_L4N/DIFFOUT_L8N)* G3(GXB_TX_R6N)* G4(GXB_TX_R6P)* G26(IO_1A_G26/DQS4L/DIFFIO_RX_L6P/DIFFOUT_L12P)* G27(IO_1A_G27/DQ4L/DIFFIO_RX_L7N/DIFFOUT_L14N)* G28(IO_1A_G28/DQS3L/DIFFIO_RX_L5P/DIFFOUT_L10P)* G29(IO_1A_G29/DQSN3L/DIFFIO_RX_L5N/DIFFOUT_L10N)* H23(NC)* H27(IO_1A_H27/DQSN4L/DIFFIO_RX_L6N/DIFFOUT_L12N)* H29(IO_1A_H29/DIFFIO_RX_L8P/DIFFOUT_L16P)* J3(GXB_CMUTX_R3N)* J4(GXB_CMUTX_R3P)* J12(NC)* J13(NC)* J14(NC)* J23(NC)* J28(IO_1C_J28/DQS5L/DIFFIO_RX_L9P/DIFFOUT_L18P)* J29(IO_1C_J29/DQSN5L/DIFFIO_RX_L9N/DIFFOUT_L18N)* J30(IO_1A_J30/DIFFIO_RX_L8N/DIFFOUT_L16N)* J31(GXB_CMUTX_L3P)* J32(GXB_CMUTX_L3N)* K12(NC)* K13(NC)* K14(NC)* K15(NC)* K20(NC)* K21(NC)* K22(NC)* K23(NC)* K28(IO_1C_K28/DQS7L/DIFFIO_RX_L12P/DIFFOUT_L24P/DATA7) K29(IO_1C_K29/DQSN7L/DIFFIO_RX_L12N/DIFFOUT_L24N/DATA6) L3(GXB_CMUTX_R2N)* L4(GXB_CMUTX_R2P)* L12(NC)* L14(NC)* L15(NC)* L20(NC)* L21(NC)* L26(IO_1C_L26/DQ5L/DIFFIO_RX_L10P/DIFFOUT_L20P)* L27(IO_1C_L27/DQ5L/DIFFIO_RX_L10N/DIFFOUT_L20N)* L31(GXB_CMUTX_L2P)* L32(GXB_CMUTX_L2N)* M13(NC)* M14(NC)* M15(NC)* M16(NC)* M17(NC)* M19(NC)* M20(NC)* N3(GXB_TX_R5N)* N4(GXB_TX_R5P)* R3(GXB_TX_R4N)* R4(GXB_TX_R4P)* T26(CLK0N_DIFFIO_RX_L14N_DIFFOUT_L28N)* U3(GXB_TX_R3N)* U4(GXB_TX_R3P)* U26(CLK0P_DIFFIO_RX_L14P_DIFFOUT_L28P)* V17(DNU)* W3(GXB_TX_R2N)* W4(GXB_TX_R2P)*

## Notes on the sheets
sheet 1
- Buttons & Switches
- LEDs
- MECHANICAL PARTS
sheet 2
- CMOS Header
sheet 3
- ADC Interface
- JESD
sheet 4
- DAC Interface
sheet 5
- USB
sheet 6
- DDR2 SO-DIMM
- Place near the DDR2 SO-DIMM
sheet 7
- BANK QL
sheet 8
- BANK1
- 2.5V
